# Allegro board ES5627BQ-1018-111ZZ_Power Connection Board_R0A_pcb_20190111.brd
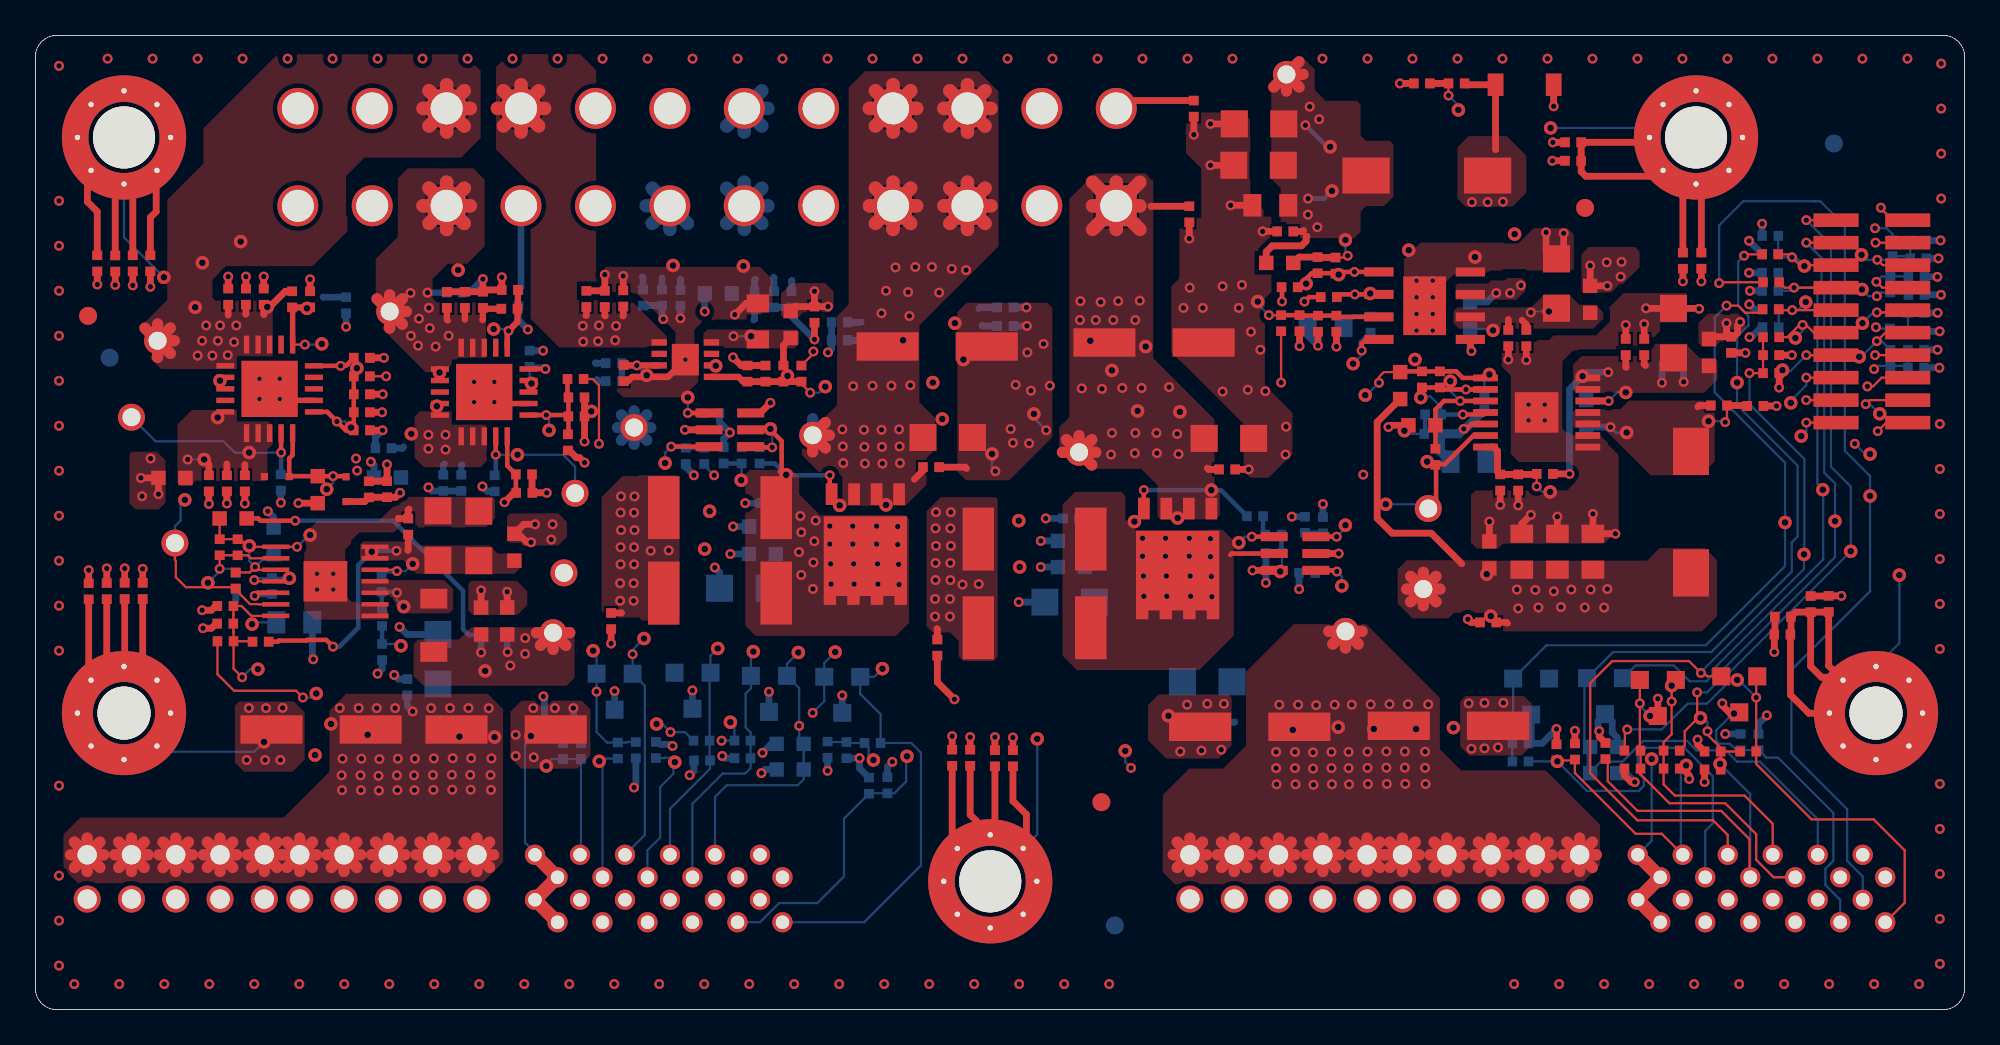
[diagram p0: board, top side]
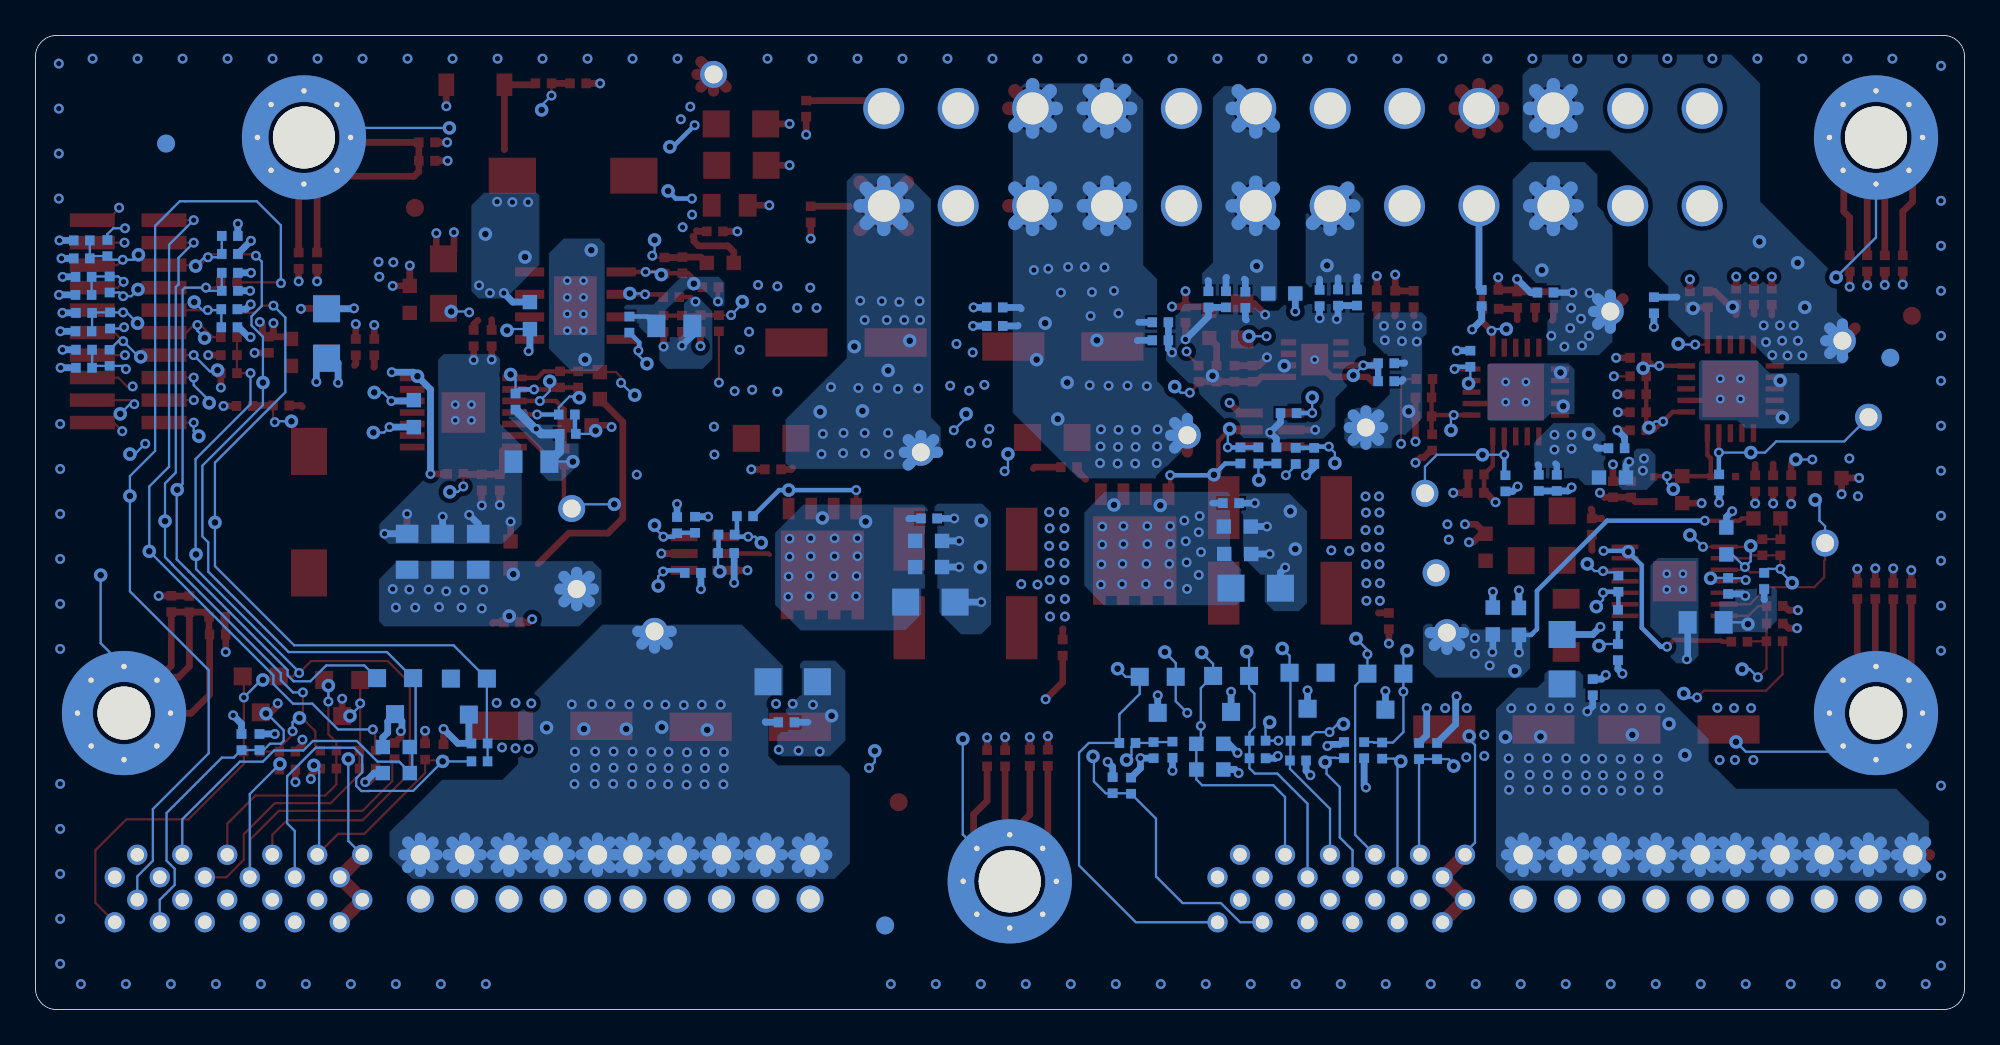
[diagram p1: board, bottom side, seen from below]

Outline 108.9 x 55 mm; copper layers: TOP, G2, S3, V4, V5, V6, G7, BOTTOM. Coordinates in mm from the lower left corner of the outline.
Outline path: 0,53.8 arc(0.35,54.65) 1.2,55 107.7,55 arc(108.55,54.65) 108.9,53.8 108.9,1.2 arc(108.55,0.35) 107.7,0 1.2,0 arc(0.35,0.35) 0,1.2 0,53.8

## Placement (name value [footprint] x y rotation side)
C1  0.1uF/16V  [CC0402]  6.06 23.64 180 top
C2  0.1uF/16V  [CC0402]  54.16 14.19 180 top
C3  0.1uF/16V  [CC0402]  4.03 23.63 180 top
C4  0.1uF/16V  [CC0402]  55.18 14.19 180 top
C5  3300pF  [CC0402]  78.85 32.5 270 bottom
C6  1uF/16V  [CC0603]  78.27 32.99 90 top
C7  22uF/16V  [CC1206]  69.07 50 270 top
C8  22uF/16V  [CC1206]  69.05 47.67 270 top
C9  22pF/50V  [CC0402]  79.28 35.58 0 top
C10  0.1uF/16V  [CC0402]  5.04 23.64 180 top
C11  0.1uF/16V  [CC0402]  3.01 23.61 180 top
C12  0.1uF/16V  [CC0402]  51.75 14.22 180 top
C13  0.1uF/16V  [CC0402]  52.77 14.22 180 top
C14  10nF/50V  [CC0402]  82.69 29.76 0 top
C15  @10uF/16V  [CC0805]  69.71 45.41 270 top
C16  0.1uF/16V  [CC0402]  70.55 43.93 270 top
C17  0.1uF/16V  [CC0402]  36.41 40.18 180 bottom
C18  0.1uF/16V  [CC0402]  82 21.86 270 top
C19  0.1uF/16V  [CC0402]  89.77 37.41 180 top
C20  1nF/50V  [CC0402]  90.82 37.41 180 top
C21  22uF/16V  [CC1206]  92.47 38.19 180 top
C22  22uF/16V  [CC1206]  92.47 38.17 0 bottom
C23  @10uF/6.3V  [CC0603]  82.08 25.67 180 top
C24  0.1uF/50V  [CC0603]  80.99 39.18 0 bottom
C25  1uF  [CC0603]  58.48 26.46 90 bottom
C26  @2200pF/50V  [CC0402]  95.03 34.1 270 top
C27  1nF/50V  [CC0402]  83.14 37.91 0 top
C28  0.1uF/16V  [CC0402]  84.16 37.91 0 top
C29  0.1uF/50V  [CC0603]  87.54 33.65 180 bottom
C30  22uF/16V  [CC1206]  85.86 40.99 180 top
C31  10uF  [CC0603]  58.48 24.99 90 bottom
C33  0.1uF/16V  [CC0402]  95.72 37.53 0 top
C34  22uF/16V  [CC1206]  51.5 32.3 270 top
C35  @0.1uF/16V  [CC0402]  41.41 28.59 90 bottom
C36  @0.1uF/16V  [CC0402]  50.56 30.62 90 top
C37  22uF/16V  [CC1206]  40.02 23.79 270 bottom
C38  @22uF/6.3V  [CC0805]  87.92 25.85 0 bottom
C39  22uF/6.3V  [CC0805]  85.91 25.85 0 bottom
C40  22uF/6.3V  [CC0805]  83.91 25.85 0 bottom
C41  0.47uF /16V  [CC0402]  73.01 40.23 270 top
C42  8200pF/16V  [CC0402]  75.37 38.68 0 bottom
C43  22pF/50V  [CC0402]  73.39 42 0 top
C45  @270uF/16V  [CAPALE_6D3PI_5D6_2SP_6D6WL7D6H]  50.9 37.44 270 top
C46  0.1uF/16V  [CC0402]  66.51 16.22 90 bottom
C47  0.1uF/16V  [CC0402]  86.8 48.96 270 top
C48  22uF/16V  [CC1206]  66.15 18.51 270 bottom
C49  0.1uF/16V  [CC0402]  4.5 42.12 0 top
C50  0.1uF/16V  [CC0402]  3.49 42.13 0 top
C51  10uF  [CC0603]  41.03 25.72 90 bottom
C54  270uF/16V  [CAPALE_6D3PI_5D6_2SP_6D6WL7D6H]  16.12 15.81 90 top
C55  270uF/16V  [CAPALE_6D3PI_5D6_2SP_6D6WL7D6H]  26.57 15.81 270 top
C56  270uF/16V  [CAPALE_6D3PI_5D6_2SP_6D6WL7D6H]  79.76 16.02 270 top
C57  270uF/16V  [CAPALE_6D3PI_5D6_2SP_6D6WL7D6H]  68.55 15.97 90 top
C58  22uF/16V  [CC1206]  22.72 19.78 180 bottom
C59  0.1uF/16V  [CC0402]  40.6 40.07 180 bottom
C60  0.1uF/16V  [CC0402]  86.8 47.92 270 top
C61  0.1uF/16V  [CC0402]  93 42.28 0 top
C62  0.1uF/16V  [CC0402]  20.99 18.2 0 bottom
C63  0.1uF/16V  [CC0402]  10.72 22.78 270 top
C64  3.3nF  [CC0402]  13.35 23.92 180 bottom
C65  @47pF  [CC0402]  11.42 26.1 0 top
C66  @0.1uF/16V  [CC0402]  67.27 30.5 90 top
C67  0.1uF/16V  [CC0402]  94.04 42.28 0 top
C68  0.1uF/16V  [CC0402]  5.5 42.13 0 top
C69  22uF/16V  [CC1206]  67.37 32.25 270 top
C70  @270uF/16V  [CAPALE_6D3PI_5D6_2SP_6D6WL7D6H]  63.15 37.66 270 top
C72  22uF/16V  [CC1206]  25.03 26.74 180 top
C73  22uF/16V  [CC1206]  22.72 26.76 180 top
C74  0.1uF/16V  [CC0402]  21.04 27.27 180 top
C75  0.1uF/16V  [CC0402]  98.61 21.18 270 top
C76  0.1uF/16V  [CC0402]  100.21 22.89 180 top
C77  0.1uF/16V  [CC0402]  98.65 22.18 270 top
C78  0.1uF/16V  [CC0402]  101.23 22.9 180 top
C79  22uF/6.3V  [CC0603]  26.63 21.94 180 top
C80  22uF/6.3V  [CC0603]  25.16 21.91 0 bottom
C83  10uF/10V  [CC0402]  12.89 40.25 180 top
C85  10uF/10V  [CC0402]  11.88 40.25 180 top
C86  0.1uF/16V  [CC0402]  10.88 40.25 180 top
C87  1000pF /50V  [CC0402]  18.43 36.8 90 top
C88  0.1uF/16V  [CC0402]  31.1 40.12 180 top
C89  0.1uF/16V  [CC0402]  18.43 32.71 90 top
C90  10uF  [CC0402]  10.81 29.71 0 top
C91  4.7uF  [CC0603]  15.94 29.35 0 top
C92  10uF  [CC0402]  11.82 29.71 0 top
C93  0.1uF/16V  [CC0402]  9.79 29.71 0 top
C94  0.1uF/16V  [CC0402]  30.54 34.56 90 top
C95  10uF  [CC0402]  27.58 30.22 90 top
C96  1000pF /50V  [CC0402]  27.9 36.75 0 bottom
C97  0.1uF/16V  [CC0402]  27.59 29.18 90 top
C98  0.1uF/16V  [CC0402]  65.14 44.9 180 top
C99  10uF  [CC0402]  24.04 29.74 180 bottom
C100  10uF/10V  [CC0402]  25.26 40.07 180 top
C101  0.1uF/16V  [CC0402]  23.02 29.74 180 bottom
C102  0.1uF/16V  [CC0402]  23.23 40.07 180 top
C103  10uF  [CC0402]  19.64 31.69 90 bottom
C104  10uF/10V  [CC0402]  24.24 40.07 180 top
C105  0.1uF/16V  [CC0402]  17.54 39.77 180 bottom
C106  0.1uF/16V  [CC0402]  23.66 40.48 90 bottom
C107  0.1uF/16V  [CC0402]  65.39 50.87 0 top
C108  0.1uF 16V  [CC0402]  43.98 39.24 180 top
C110  0.1uF/16V  [CC0402]  27.26 40.18 0 bottom
C111  10uF/16V  [CC0805]  40.78 38.85 0 top
C113  0.1uF/16V  [CC0402]  40.19 35.91 180 top
C115  0.1uF/16V  [CC0402]  45.4 37.79 90 bottom
C116  0.1uF/16V  [CC0402]  34.3 40.2 0 bottom
C117  0.1uF/16V  [CC0402]  35.37 40.2 180 bottom
C118  0.1uF/16V  [CC0402]  54.75 38.6 90 bottom
C119  0.1uF/16V  [CC0402]  33.18 40.15 180 top
C120  0.1uF/16V  [CC0402]  41.69 40.1 180 bottom
C121  0.1uF/16V  [CC0402]  42.68 40.1 0 bottom
C122  0.1uF/16V  [CC0402]  54.75 39.64 90 bottom
C123  10uF/10V  [CC0402]  32.14 40.12 180 top
C124  100pF  [CC0402]  32.65 36.49 90 bottom
C127  0.1uF/16V  [CC0402]  45.4 38.8 90 bottom
C128  @0.1uF/16V  [CC0402]  58.46 27.73 90 bottom
C129  22uF/16V  [CC1206]  58.38 23 270 bottom
C131  0.1uF/16V  [CC0402]  32.5 21.94 0 top
C132  0.22uF  [CC0402]  38.16 33.67 270 bottom
C133  0.01uF/25V  [CC0402]  38.85 31.29 180 bottom
C134  0.1uF/16V  [CC0402]  50.91 20.44 0 top
C135  0.22uF  [CC0402]  71.79 24.66 90 bottom
C136  0.01uF/25V  [CC0402]  69.91 25.77 270 bottom
C137  1uF  [CC0603]  41.06 27.27 90 bottom
CB3  @2200pF/50V  [CC0402]  78.27 52.29 270 top
CB4  0.1uF/16V  [CC0402]  72.4 38.73 180 top
CB5  @22uF/6.3V  [CC0805]  83.91 25.85 180 top
CB6  22uF/6.3V  [CC0805]  85.91 25.85 180 top
CB7  @22uF/6.3V  [CC0805]  87.92 25.85 180 top
CB8  0.1uF/16V  [CC0402]  6.49 42.13 0 top
CB9  1uF/16V  [CC0603]  13.45 26.46 180 bottom
CB10  0.1uF/25V  [CC0402]  19.54 24.05 180 bottom
CB11  22uF/6.3V  [CC0603]  26.63 21.94 0 bottom
CB12  0.1UF /50V  [CC0603]  25.16 21.94 180 top
CB13  0.1uF/16V  [CC0402]  19.85 29.38 180 top
CB14  10uF  [CC0402]  18.82 29.37 180 top
CB54  @2.2nF  [CC0402]  19.57 20.19 0 bottom
CONN1  @Vmonitor_3V3_PG  [CONN_1DP_2D54WL8D94H_PIP]  78.63 28.29 0 top
CONN2  @USB_VCC5P0  [CONN_1DP_2D54WL8D94H_PIP]  70.62 52.8 180 top
CONN4  @Vmonitor_3V3  [CONN_1DP_2D54WL8D94H_PIP]  78.35 23.74 0 top
CONN5  @VCC12  [CONN_1DP_2D54WL8D94H_PIP]  43.88 32.43 270 top
CONN6  @PSU2_VCC12  [CONN_1DP_2D54WL8D94H_PIP]  73.95 21.35 0 top
CONN7  @PSU1_VCC12  [CONN_1DP_2D54WL8D94H_PIP]  29.83 24.66 0 top
CONN8  @Heater_VCC12  [CONN_1DP_2D54WL8D94H_PIP]  58.92 31.46 0 top
CONN9  @FPGA_1V2_PG  [CONN_1DP_2D54WL8D94H_PIP]  7.87 26.34 0 top
CONN10  @FPGA_1V2  [CONN_1DP_2D54WL8D94H_PIP]  29.22 21.28 0 top
CONN11  @CPLD_VDD1P8  [CONN_1DP_2D54WL8D94H_PIP]  6.9 37.76 0 top
CONN13  @CPLD_VDD1P8_PG  [CONN_1DP_2D54WL8D94H_PIP]  5.42 33.44 0 top
CONN14  @MANG_1P2_PG  [CONN_1DP_2D54WL8D94H_PIP]  30.46 29.15 180 top
CONN15  @MANG_1P2  [CONN_1DP_2D54WL8D94H_PIP]  20 39.41 180 top
CONN16  @FPGA_2V5  [CONN_1DP_2D54WL8D94H_PIP]  33.79 32.86 0 top
CONN19  LCB25-G2024S01C-04  [CONNM_1D27X4D05_2X10SP_27D2W]  103.67 38.85 90 top
CONN20  MINI-FIT  [CONN_4D2X5D5_12X2DP_52W_PIP]  37.91 48.13 0 top
CONNB1  HI POWER  [CONN_2D54_44DP_43D7W7D5H_PIP]  40.9 8.74 180 bottom
CONNB2  HI POWER  [CONN_2D54_44DP_43D7W7D5H_PIP]  103.15 8.74 180 bottom
D1  BAT54TS  [SOD523_1D4_2SP_1D2WD8L]  17.54 29.38 90 top
DB1  @SS1040  [SOD123_3D28_2SP_AC]  84.06 52.21 90 top
DB2  BAT54TS  [SOD523_1D4_2SP_1D2WD8L]  13.62 30.09 0 top
H1  SCREW_8_2  [MTH_276C118D_8DP_OSP]  5 16.74 0 top
H2  SCREW_8_2  [MTH_276C138D_8DP_OSP]  53.9 7.24 0 top
H3  SCREW_8_2  [MTH_276C138D_8DP_OSP]  93.74 49.24 0 top
H4  SCREW_8_2  [MTH_276C138D_8DP_OSP]  5 49.24 0 top
H5  SCREW_8_2  [MTH_276C118D_8DP_OSP]  103.9 16.74 0 top
L1  3.3uH/9.5A/22mohm  [IND_6D1_2SP_7D3W7D5L6H_1]  78.55 47.08 180 top
L2  100MHz /5A  [LC0603]  94.47 37.1 0 top
L3  2.2uH  [IND_6D1_2SP_7D3W7D5L6H_1]  93.46 28.08 270 top
L4  100MHz/5A  [LC0603]  38.54 40.43 90 bottom
L5  100MHz/3A  [LC0603]  27.04 26.1 180 top
L6  2.2uH/ 3.5A 65mohm  [IND_3D_2SP_3D5W3D2L2H]  22.49 21.7 90 top
L7  100MHz/3A  [LC0603]  7.71 30.02 90 top
L8  100MHz/3A  [LC0603]  19.87 30.04 270 bottom
L9  100MHz/3A  [LC0603]  42.63 38.68 0 top
LB1  100MHz/3A  [LC0603]  87.77 40.1 0 top
NOREF  -  []  14.81 45.38 0 top
NOREF#2  -  []  0 0 0 top
NOREF#3  -  []  103.67 38.85 0 top
NOREF#4  -  [unnamed#2]  2.97 39.17 0 top
NOREF#5  -  []  93.74 49.24 0 top
NOREF#6  -  []  2.92 8.74 0 top
NOREF#7  -  []  5 16.74 0 top
NOREF#8  -  []  103.9 16.74 0 top
NOREF#9  -  []  65.17 8.74 0 top
NOREF#10  -  []  107.7 55 0 top
NOREF#11  -  []  2.92 8.74 0 top
NOREF#12  -  []  5 49.24 0 top
NOREF#13  -  []  53.9 7.24 0 top
NOREF#14  -  []  -286.37 -149.01 0 top
NOREF#15  -  []  93.74 49.24 0 top
NOREF#16  -  [unnamed#2]  87.48 45.26 0 top
NOREF#17  -  []  5 49.24 0 top
NOREF#18  -  []  103.9 16.74 0 top
NOREF#19  -  []  53.9 7.24 0 top
NOREF#20  -  []  -319.22 -224.39 0 top
NOREF#21  -  []  61.72 -23.77 0 top
NOREF#22  -  []  14.81 45.38 0 top
NOREF#23  -  []  0 0 0 top
NOREF#24  -  [unnamed#2]  60.17 11.71 0 top
NOREF#25  -  []  5 16.74 0 top
NOREF#26  -  []  108.9 1.2 0 top
NOREF#27  -  []  65.17 8.74 0 top
NOREF#28  -  []  103.67 38.85 0 top
NOREF#29  -  []  94.52 27.73 180 bottom
NOREF#30  -  [unnamed#2]  101.52 48.9 180 bottom
NOREF#31  -  [unnamed#2]  60.93 4.75 180 bottom
NOREF#32  -  []  66.89 47.69 180 bottom
NOREF#33  -  [unnamed#2]  4.19 36.8 180 bottom
Q3  PJMBZ6V2  [SOT23_3SP_C1_C2_A]  41.41 17.82 0 bottom
Q4  PJMBZ6V2  [SOT23_3SP_C1_C2_A]  45.55 17.77 0 bottom
Q5  PJMBZ6V2  [SOT23_3SP_C1_C2_A]  91.58 17.59 180 top
Q6  PJMBZ6V2  [SOT23_3SP_C1_C2_A]  88.6 17.7 0 bottom
Q7  PJMBZ6V2  [SOT23_3SP_C1_C2_A]  32.69 17.95 0 bottom
Q8  PJMBZ6V2  [SOT23_3SP_C1_C2_A]  37.09 18 0 bottom
Q11  N-CH  [SO8_3D75X1D27_5SP]  46.85 26.28 90 top
Q12  N-CH  [SO8_3D75X1D27_5SP]  64.48 25.46 90 top
QB1  PJMBZ6V2  [SOT23_3SP_C1_C2_A]  96.18 17.8 180 top
QB2  PJMBZ6V2  [SOT23_3SP_C1_C2_A]  84.43 17.67 0 bottom
R1  22.1K  [RC0402]  81.8 34.33 180 bottom
R2  73.2K  [RC0402]  78.27 35.58 180 top
R3  0  [RC0402]  78.9 33.6 90 bottom
R4  100K  [RC0402]  79.03 31.21 180 top
R5  10ohm  [RC0603]  77.04 35.23 0 top
R6  0ohm 0805  [RC0805]  80.9 30.94 90 bottom
R7  @10K  [RC0402]  83.7 29.76 180 top
R8  10K  [RC0402]  85.2 30.24 270 top
R9  @2.2  [RC0402]  97.09 34.08 90 top
R12  0ohm 0805  [RC0805]  72.83 38.6 270 bottom
R13  22.1Kohm  [RC0402]  70.8 40.78 90 top
R14  0  [RC0402]  71.36 38.75 0 top
R15  @0  [RC0402]  70.32 38.75 0 top
R16  124Kohm  [RC0402]  72.38 42.03 180 top
R17  10ohm  [RC0603]  70.24 42.16 270 top
R18  @4.7K  [RC0402]  97.93 43.68 270 bottom
R19  @4.7K  [RC0402]  97.93 42.66 90 bottom
R20  @10K  [RC0402]  106.18 38.3 90 bottom
R21  @4.7K  [RC0402]  106.16 39.34 270 bottom
R22  10  [RC0402]  104.71 36.8 180 bottom
R24  9.1K  [RC0603]  88.53 14.83 90 bottom
R25  @10K  [RC0603]  88.53 13.35 270 bottom
R26  @10K  [RC0603]  42.61 13.56 90 bottom
R27  9.1K  [RC0603]  42.61 15 270 bottom
R28  10  [RC0402]  104.84 42.99 0 bottom
R29  @4.7K  [RC0402]  106.28 42.41 270 bottom
R30  @4.7K  [RC0402]  106.28 43.43 90 bottom
R31  510  [RC0402]  106.18 41.37 270 bottom
R32  @4.7K  [RC0402]  45.78 14.65 180 bottom
R33  4.7K  [RC0402]  44.71 14.67 0 bottom
R34  10  [RC0402]  47.25 15.05 270 bottom
R35  0  [RC0402]  92.36 14.62 90 top
R36  0  [RC0402]  90.16 14.62 270 top
R37  10  [RC0402]  97.93 42.64 270 top
R38  @1000  [RC0402]  97.93 41.6 270 bottom
R39  510  [RC0402]  97.93 40.58 90 bottom
R40  10  [RC0402]  104.68 38.91 180 bottom
R41  3.83Kohm  [RC0402]  33.89 14.65 180 bottom
R42  100ohm  [RC0402]  106.16 36.24 90 bottom
R43  @4.7K  [RC0402]  106.16 37.25 270 bottom
R44  0  [RC0402]  35.03 14.66 0 bottom
R45  0  [RC0402]  37.6 15.18 90 bottom
R46  0  [RC0402]  39.91 15.18 90 bottom
R47  4.7K(1%)  [RC0402]  47.05 12.64 180 bottom
R48  @1000  [RC0402]  106.18 40.35 90 bottom
R49  4.7K(1%)  [RC0402]  29.78 14.6 0 bottom
R51  10  [RC0402]  97.98 41.06 270 top
R52  @680(1%)  [RC0402]  48.09 12.67 180 bottom
R53  10  [RC0402]  104.71 40.94 180 bottom
R54  @680(1%)  [RC0402]  30.8 14.6 0 bottom
R55  0  [RC0402]  32.88 14.62 0 bottom
R56  @1K  [RC0402]  12.71 20.77 90 top
R57  0  [RC0402]  10.73 20.79 270 top
R58  1K  [RC0402]  10.72 21.79 90 top
R59  100K  [RC0402]  11.3 24.23 180 top
R60  22.1K  [RC0402]  11.31 24.2 0 bottom
R61  12.7Kohm  [RC0402]  10.4 26.1 180 top
R62  10ohm  [RC0603]  11.16 27.73 90 top
R63  2.87K  [RC0402]  15.5 40.1 0 top
R64  3.57K  [RC0402]  14.49 40.1 0 top
R65  0  [RC0402]  18.43 35.76 90 top
R66  @4.7K  [RC0402]  18.43 34.74 270 top
R67  10K  [RC0402]  13.85 29.76 0 bottom
R68  1K(5%)  [RC0402]  30.54 33.49 270 top
R69  4.99K  [RC0402]  26.78 40.63 90 top
R70  2.49K  [RC0402]  26.76 39.57 90 top
R71  10K  [RC0402]  25.92 29.71 0 bottom
R72  @1K  [RC0402]  42.23 35.91 180 top
R73  1K  [RC0402]  41.21 35.91 0 top
R74  0  [RC0402]  43.24 35.91 180 top
R75  39.2K  [RC0402]  32.65 35.48 90 bottom
R76  36.5K  [RC0402]  33.21 35.93 180 top
R78  10K  [RC0402]  36.71 31.26 180 bottom
R79  10K  [RC0402]  37.75 31.26 180 bottom
R80  100  [RC0402]  39.86 31.29 180 bottom
R81  100  [RC0402]  40.88 31.29 180 bottom
R83  10K  [RC0402]  72.68 27.35 0 bottom
R84  1.5K  [RC0402]  71.66 27.37 0 bottom
R85  100  [RC0402]  69.89 26.81 270 bottom
R86  100  [RC0402]  68.84 27.86 90 bottom
R87  0.002ohm\1W/2512  [RC2512]  38.64 28.34 90 top
R88  0.002ohm\1W/2512  [RC2512]  38.64 23.51 90 top
R90  0.002ohm\1W/2512  [RC2512]  56.4 21.56 90 top
R91  @4.7K  [RC0402]  37.63 14.06 90 bottom
R92  @4.7K  [RC0402]  39.91 14.19 90 bottom
R93  @4.7K  [RC0402]  92.36 13.61 90 top
R94  @4.7K  [RC0402]  90.16 13.61 270 top
R95  0.002ohm\1W/2512  [RC2512]  56.4 26.56 90 top
RB2  @2.2  [RC0402]  80.22 52.29 90 top
RB3  1K(5%)  [RC0402]  73.44 38.73 180 top
RB5  @10K  [RC0402]  97.95 39.54 270 bottom
RB6  @4.7K  [RC0402]  97.95 38.52 90 bottom
RB7  10  [RC0402]  97.95 39.54 270 top
RB8  100ohm  [RC0402]  97.98 36.95 270 top
RB9  @4.7K  [RC0402]  97.98 35.93 90 top
RB10  10  [RC0402]  97.98 37.97 270 top
RB11  10  [RC0402]  96.68 14.57 90 top
RB12  @4.7K  [RC0402]  94.68 14.57 270 top
RB13  4.7K  [RC0402]  94.68 13.56 90 top
RB14  3.83Kohm  [RC0402]  83.83 15.03 270 bottom
RB15  @4.7K  [RC0402]  86.9 14.57 180 top
RB16  @4.7K  [RC0402]  96.25 15.11 180 bottom
RB17  680(1%)  [RC0402]  97.27 15.11 180 bottom
RB18  0  [RC0402]  83.83 14.01 90 bottom
RB19  680(1%)  [RC0402]  85.86 14.52 180 top
RB20  0  [RC0402]  88.63 14.6 180 top
RB21  0ohm 0805  [RC0805]  14.62 21.86 270 bottom
RB22  1K(5%)  [RC0402]  18.43 33.72 270 top
RB23  @4.7K  [RC0402]  30.06 32.02 180 top
RB24  0  [RC0402]  30.49 35.6 90 top
RB25  @1.5ohm  [RC0402]  19.57 22.12 180 bottom
U1  TPS54626PWPR  [TSSOP_D65X5D775_14SP_4D4W5L_G1]  84.74 33.71 0 top
U2  TPS54329DDAR  [SOP_1D27X5D165_8SP_3D9W_G95X130]  78.42 39.74 180 top
U3  TPS54226PWPR  [TSSOP_D65X5D6_14SP_GP]  16.37 24.18 0 top
U4  TPS74801RGWR  [QFN_D65X5D_20SP_5WL_G1]  13.22 35.04 90 top
U5  TPS74801RGWR  [QFN_D65X5D_20SP_5WL_G1]  25.33 34.87 90 top
U6  TPS73701DRBR  [QFN_D65X2D95_8SP_3WL1H_G1]  36.69 36.7 0 top
U7  ADM4210-1AUJ-RL7  [SOT23_D95X2D35_6SP_1D6W2D9L]  39.2 32.73 270 top
U8  ADM4210-1AUJ-RL7  [SOT23_D95X2D35_6SP_1D6W2D9L]  71.11 25.75 90 top

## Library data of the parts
C1-C31 C33-C43 C46-C51 C58-C69 C75-C80 C83 C85-C108 C110 C113 C115-C124 C127-C129 C132 C135 C137 CB3-CB8 CB10 CB11 CB13 CB14 CB54 = C_NP
C45 C54-C57 C70 = C_P
C72 C73 C131 C134 CB9 = CAP NP
C74 = C_NP: room: U119
C111 CB12 = C_NP: room: 1
C133 C136 = C_NP: room: VCC10
CONN1 CONN2 CONN4-CONN11 CONN13-CONN16 = PINSTICK_MALE_1PX1R
CONN19 = PIN HEADER_MALE_10PX2R
CONN20 = CONN_POWER_MALE_12PX2R
CONNB1 CONNB2 = CONN_POWER_FEMALE_DIP44_2
D1 DB1 DB2 = DIODE1_1
H1-H5 = SCREW_8_1
L1 L3 L6 = POWER CHOKE
L2 L4 L5 L7-L9 LB1 = BEAD
Q3-Q8 QB1 QB2 = DIODE2_3
Q11 Q12 = NMOS1_6
R1-R7 R9 R12 R13 R16 R17 R24-R27 R35 R36 R41 R44-R47 R49 R52 R54-R56 R58-R64 R66 R68-R70 R72 R73 R75 R76 R80 R81 R85-R88 R90-R95 RB2 RB3 RB14-RB23 RB25 = R: tolerance: 1%
R8 R67 R71 = R: tolerance: 1%; room: 71
R14 R15 R57 R65 R74 RB24 = R: tolerance: 1%; room: U120
R18-R22 R28-R34 R37-R40 R42 R43 R48 R51 R53 RB5-RB13 = R: tolerance: 1%; room: U111
R78 R79 R83 R84 = R
U1 = DC_DC_TI_TPS54626
U2 = DC_DC_MPS_MP1484EN-C166_0
U3 = DC_DC_TI_TPS54226_PWP
U4 U5 = LDO_TI_TPS74801RGW_1
U6 = LDO_TI_TPS73701
U7 U8 = HOT SWAP_ADI_ADM4210-1AUJ

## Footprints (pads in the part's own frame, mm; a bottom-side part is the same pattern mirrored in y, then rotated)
CAPALE_6D3PI_5D6_2SP_6D6WL7D6H
  rect 1.6x3.505 smd: A(0,-2.8) C(0,2.8)
CC0402
  rect 0.559x0.539 smd: 1(0,0.454) 2(0,-0.454)
CC0603
  rect 0.813x0.813 smd: 1(0,0.762) 2(0,-0.762)
CC0805
  rect 1.27x1.016 smd: 1(0,1.016) 2(0,-1.016)
CC1206
  rect 1.524x1.524 smd: 1(0,1.397) 2(0,-1.397)
CONN_1DP_2D54WL8D94H_PIP
  round 1.524 hole 1.016: 1(0,0)
CONN_2D54_44DP_43D7W7D5H_PIP
  round 1.143 hole 0.762: 1(-1.27,-3.81) 2(0,-2.54) 3(1.27,-3.81) 4(2.54,-2.54) 5(3.81,-3.81) 6(5.08,-2.54) 7(6.35,-3.81) 8(7.62,-2.54) 9(8.89,-3.81) 10(10.16,-2.54) 11(11.43,-3.81) 12(12.7,-2.54) 13(12.7,0) 14(11.43,-1.27) 15(10.16,0) 16(8.89,-1.27) 17(7.62,0) 18(6.35,-1.27) 19(5.08,0) 20(3.81,-1.27) 21(2.54,0) 22(1.27,-1.27) 23(0,0) 24(-1.27,-1.27)
  round 1.524 hole 1.092: P1A_1(15.98,-2.5) P1A_2(18.48,-2.5) P1A_3(20.98,-2.5) P1A_4(23.48,-2.5) P1A_5(25.98,-2.5) P1B_1(15.98,0) P1B_2(18.48,0) P1B_3(20.98,0) P1B_4(23.48,0) P1B_5(25.98,0) P2A_1(27.98,-2.5) P2A_2(30.48,-2.5) P2A_3(32.98,-2.5) P2A_4(35.48,-2.5) P2A_5(37.98,-2.5) P2B_1(27.98,0) P2B_2(30.48,0) P2B_3(32.98,0) P2B_4(35.48,0) P2B_5(37.98,0)
CONN_4D2X5D5_12X2DP_52W_PIP
  rect 2.311x2.311 hole 1.803: 1(23.1,-2.75)
  round 2.311 hole 1.803: 2(18.9,-2.75) 3(14.7,-2.75) 4(10.5,-2.75) 5(6.3,-2.75) 6(2.1,-2.75) 7(-2.1,-2.75) 8(-6.3,-2.75) 9(-10.5,-2.75) 10(-14.7,-2.75) 11(-18.9,-2.75) 12(-23.1,-2.75) 13(23.1,2.75) 14(18.9,2.75) 15(14.7,2.75) 16(10.5,2.75) 17(6.3,2.75) 18(2.1,2.75) 19(-2.1,2.75) 20(-6.3,2.75) 21(-10.5,2.75) 22(-14.7,2.75) 23(-18.9,2.75) 24(-23.1,2.75)
CONNM_1D27X4D05_2X10SP_27D2W
  rect 0.762x2.54 smd: 1(-5.715,-2.025) 2(-5.715,2.025) 3(-4.445,-2.025) 4(-4.445,2.025) 5(-3.175,-2.025) 6(-3.175,2.025) 7(-1.905,-2.025) 8(-1.905,2.025) 9(-0.635,-2.025) 10(-0.635,2.025) 11(0.635,-2.025) 12(0.635,2.025) 13(1.905,-2.025) 14(1.905,2.025) 15(3.175,-2.025) 16(3.175,2.025) 17(4.445,-2.025) 18(4.445,2.025) 19(5.715,-2.025) 20(5.715,2.025)
IND_3D_2SP_3D5W3D2L2H
  rect 1.118x1.524 smd: 1(1.5,0) 2(-1.5,0)
IND_6D1_2SP_7D3W7D5L6H_1
  rect 2.667x2.032 smd: 1(-3.431,0) 2(3.431,0)
LC0603
  rect 0.813x0.813 smd: 1(0,0.762) 2(0,-0.762)
MTH_276C118D_8DP_OSP
  round 2.997 hole 2.997 unplated: (0,0)
  round 0.889 hole 0.305: 1(0,2.629) 2(1.859,1.859) 3(2.629,0) 4(1.859,-1.859) 5(0,-2.629) 6(-1.859,-1.859) 7(-2.629,0) 8(-1.859,1.859)
MTH_276C138D_8DP_OSP
  round 3.505 hole 3.505 unplated: (0,0)
  round 0.889 hole 0.305: 1(0,2.629) 2(1.859,1.859) 3(2.629,0) 4(1.859,-1.859) 5(0,-2.629) 6(-1.859,-1.859) 7(-2.629,0) 8(-1.859,1.859)
QFN_D65X2D95_8SP_3WL1H_G1
  rect 0.864x0.356 smd: 1(-1.475,0.975) 2(-1.475,0.325) 3(-1.475,-0.325) 4(-1.475,-0.975) 5(1.475,-0.975) 6(1.475,-0.325) 7(1.475,0.325) 8(1.475,0.975)
  rect 1.524x1.778 smd: G1(0,0)
QFN_D65X5D_20SP_5WL_G1
  rect 0.305x1.016 smd: 1(1.3,2.5) 2(0.65,2.5) 3(0,2.5) 4(-0.65,2.5) 5(-1.3,2.5) 11(-1.3,-2.5) 12(-0.65,-2.5) 13(0,-2.5) 14(0.65,-2.5) 15(1.3,-2.5)
  rect 1.016x0.305 smd: 6(-2.5,1.3) 7(-2.5,0.65) 8(-2.5,0) 9(-2.5,-0.65) 10(-2.5,-1.3) 16(2.5,-1.3) 17(2.5,-0.65) 18(2.5,0) 19(2.5,0.65) 20(2.5,1.3)
  rect 3.175x3.175 smd: G1(0,0)
RC0402
  rect 0.559x0.539 smd: 1(0,0.454) 2(0,-0.454)
RC0603
  rect 0.813x0.813 smd: 1(0,0.762) 2(0,-0.762)
RC0805
  rect 1.27x1.016 smd: 1(0,1.016) 2(0,-1.016)
RC2512
  rect 3.556x1.778 smd: 1(0,3.175) 2(0,-3.175)
SO8_3D75X1D27_5SP
  rect 1.219x0.66 smd: 1(2.825,-1.905) 2(2.825,-0.635) 3(2.825,0.635) 4(2.825,1.905)
  custom 1.175x1.175 smd: 5(-0.925,0)
SOD123_3D28_2SP_AC
  rect 1.27x0.889 smd: A(0,-1.64) C(0,1.64)
SOD523_1D4_2SP_1D2WD8L
  rect 0.406x0.406 smd: A(-0.7,0) C(0.7,0)
SOP_1D27X5D165_8SP_3D9W_G95X130
  rect 1.651x0.508 smd: 1(-2.582,1.905) 2(-2.582,0.635) 3(-2.582,-0.635) 4(-2.582,-1.905) 5(2.582,-1.905) 6(2.582,-0.635) 7(2.582,0.635) 8(2.582,1.905)
  rect 2.413x3.302 smd: G1(0,0)
SOT23_3SP_C1_C2_A
  rect 1.016x1.016 smd: A(0,1.016) C1(-1.016,-1.016) C2(1.016,-1.016)
SOT23_D95X2D35_6SP_1D6W2D9L
  rect 0.508x1.524 smd: 1(-0.95,-1.175) 2(0,-1.175) 3(0.95,-1.175) 4(0.95,1.175) 5(0,1.175) 6(-0.95,1.175)
TSSOP_D65X5D6_14SP_GP
  rect 1.524x0.254 smd: 1(-2.8,1.95) 2(-2.8,1.3) 3(-2.8,0.65) 4(-2.8,0) 5(-2.8,-0.65) 6(-2.8,-1.3) 7(-2.8,-1.95) 8(2.8,-1.95) 9(2.8,-1.3) 10(2.8,-0.65) 11(2.8,0) 12(2.8,0.65) 13(2.8,1.3) 14(2.8,1.95)
  rect 2.464x2.286 smd: G1(0,0)
TSSOP_D65X5D775_14SP_4D4W5L_G1
  rect 1.397x0.381 smd: 1(-2.887,1.95) 2(-2.887,1.3) 3(-2.887,0.65) 4(-2.887,0) 5(-2.887,-0.65) 6(-2.887,-1.3) 7(-2.887,-1.95) 8(2.887,-1.95) 9(2.887,-1.3) 10(2.887,-0.65) 11(2.887,0) 12(2.887,0.65) 13(2.887,1.3) 14(2.887,1.95)
  rect 2.464x2.286 smd: G1(0,0)
unnamed#2
  round 1.016 smd: (0,0)

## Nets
5VSTB1: CONNB1.11(+5VSB#3) CONNB1.12(+5VSB#2) CONNB1.13(+5VSB#0) CONNB1.14(+5VSB#1)
5VSTB2: CONNB2.11(+5VSB#3) CONNB2.12(+5VSB#2) CONNB2.13(+5VSB#0) CONNB2.14(+5VSB#1)
AGND_FPGA_1V2: C64.2 R60.1 RB21.1 U3.5(GND)
GND: C1.2 C2.2 C3.2 C4.2 C6.1 C7.2 C8.2 C10.2 C11.2 C12.2 C13.2 C14.2 C15.2 C16.2 C17.2 C18.2 C19.2 C20.2 C21.2 C22.2 C23.2 C25.2 C27.2 C28.2 C30.2 C31.2 C33.2 C34.1 C35.2 C36.2 C37.1 C38.2 C39.2 C40.2 C41.2 C45.C C46.2 C47.2 C48.1 C49.2 C50.2 C51.2 C54.C C55.C C56.C C57.C C58.1 C59.2 C60.2 C61.2 C62.2 C63.2 C66.2 C67.2 C68.2 C69.1 C70.C C72.2 C73.2 C74.2 C75.2 C76.2 C77.2 C78.2 C79.2 C80.2 C83.2 C85.2 C86.2 C87.2 C88.2 C89.2 C90.2 C91.2 C92.2 C93.2 C94.2 C95.2 C96.2 C97.2 C98.1 C99.2 C100.2 C101.2 C102.2 C103.2 C104.2 C105.2 C106.1 C107.2 C108.1 C110.1 C111.1 C113.2 C115.2 C116.1 C117.2 C118.1 C119.2 C120.2 C121.1 C122.1 C123.2 C127.2 C128.2 C129.1 C131.2 C132.2 C133.1 C134.2 C135.2 C136.1 C137.2 CB3.2 CB4.1 CB5.2 CB6.2 CB7.2 CB8.2 CB9.1 CB11.2 CB12.2 CB13.2 CB14.2 CB54.1 CONN20.2 CONN20.5 CONN20.8 CONN20.11 CONN20.12 CONN20.14 CONN20.17 CONN20.20 CONN20.23 CONN20.24 CONNB1.P1A_1(GND#9) CONNB1.P1A_2(GND#8) CONNB1.P1A_3(GND#7) CONNB1.P1A_4(GND#6) CONNB1.P1A_5(GND#5) CONNB1.P2A_1(GND#4) CONNB1.P2A_2(GND#3) CONNB1.P2A_3(GND#2) CONNB1.P2A_4(GND#1) CONNB1.P2A_5(GND#0) CONNB2.P1A_1(GND#9) CONNB2.P1A_2(GND#8) CONNB2.P1A_3(GND#7) CONNB2.P1A_4(GND#6) CONNB2.P1A_5(GND#5) CONNB2.P2A_1(GND#4) CONNB2.P2A_2(GND#3) CONNB2.P2A_3(GND#2) CONNB2.P2A_4(GND#1) CONNB2.P2A_5(GND#0) DB1.A Q3.A Q4.A Q5.A Q6.A Q7.A Q8.A QB1.A QB2.A R6.1 R7.1 R9.2 R12.1 R18.1 R20.1 R24.1 R27.1 R30.1 R33.1 R38.1 R41.2 R42.1 R44.2 R48.1 R52.1 R54.2 R58.1 R63.1 R68.1 R69.1 R73.1 R76.1 R78.2 R83.2 RB3.1 RB5.1 RB8.1 RB13.1 RB14.2 RB17.1 RB19.2 RB20.2 RB21.2 RB22.1 U1.8(PGND1) U1.9(PGND2) U1.G1(PWGD) U2.4(GND) U2.G1 U3.8(PGND#1) U3.9(PGND#2) U3.G1(PWRPD) U4.12(GND) U4.G1 U5.12(GND) U5.G1 U6.4(GND1) U6.G1(GND PAD) U7.2(GND) U8.2(GND)
VCC12: C34.2 C36.1 C45.A C115.1 C118.2 C122.2 C127.1 CONN5.1 CONN20.3 CONN20.4 CONN20.15 CONN20.16 Q11.1(S1) Q11.2(S2) Q11.3(S3)
BS_USB_VCC5P0: C24.1 U2.1(BS)
BS_VSTB_3V3: C29.1 U1.12(VBST)
CPLD_VDD1P8: C83.1 C85.1 C86.1 C105.1 CONN11.1 CONN20.22 R64.1 U4.1(VOUT1) U4.18(VOUT2) U4.19(VOUT3) U4.20(VOUT4)
CPLD_VDD1P8_FB: R63.2 R64.2 U4.16(FB)
CPLD_VDD1P8_PG: CONN13.1 CONN19.4 R67.2 U4.9(PG)
CPLD_VDD1P8_SS: C87.1 U4.15(SS)
CPLD_VDD1P8_VIN: C90.1 C92.1 C93.1 DB2.A L7.2 U4.5(VIN1) U4.6(VIN2) U4.7(VIN3) U4.8(VIN4)
EN_CPLD_VDD1P8_R: C89.1 R65.1 R66.2 RB22.2 U4.11(EN)
EN_MANG_1P2_R: C94.1 R68.2 RB23.2 RB24.1 U5.11(EN)
EN_USB_VCC5P0_R: CB4.2 R14.1 R15.1 RB3.2 U2.7(EN)
FB_USB_VCC5P0: C43.2 R13.2 R16.1 U2.5(FB)
FB_VSTB_3V3: C9.2 R1.1 R2.1 U1.2(VFB)
FPGA_1V2: C79.1 C80.1 C110.2 CB11.1 CB12.1 CONN10.1 CONN20.9 L6.2 R62.2
FPGA_1V2_BST: CB10.1 U3.12(VBST)
FPGA_1V2_EN_R: C63.1 R56.1 R57.1 R58.2 U3.7(EN)
FPGA_1V2_FB: C65.2 R60.2 R61.1 U3.2(VFB)
FPGA_1V2_PG: CONN9.1 R59.1 U3.6(PG)
FPGA_1V2_SS: C64.1 U3.4(SS)
FPGA_1V2_SW: CB10.2 L6.1 RB25.1 U3.10(SW1) U3.11(SW2)
FPGA_1V2_VIN: C72.1 C73.1 C74.1 L5.1 R56.2 U3.13(VIN) U3.14(VCC)
FPGA_1V2_VO: C65.1 R61.2 R62.1 U3.1(VO)
FPGA_1V2_VREG5: CB9.2 R59.2 U3.3(VREG5)
FPGA_2V5: C88.1 C119.1 C123.1 C124.2 CONN16.1 CONN20.21 R75.2 U6.1(OUT)
FPGA_2V5_EN: C113.1 R72.1 R73.2 R74.1 U6.5(EN)
FPGA_2V5_FB: C124.1 R75.1 R76.2 U6.3(NR/FB)
FPGA_2V5_IN: C111.2 L9.2 R72.2 U6.8(IN)
HEATER_VCC12: C33.1 C66.1 C69.2 C70.A C98.2 CONN8.1 CONN20.1 L2.1 L5.2 LB1.1 Q12.1(S1) Q12.2(S2) Q12.3(S3)
HGATE_MB1: Q11.4(G) R81.2
HGATE_MB2: Q12.4(G) R86.2
I2C_SCL_PS1: CONNB1.19(SCL) Q8.C2 R45.1 R91.1
I2C_SCL_PS2: CONNB2.19(SCL) Q5.C1 R35.1 R93.1
I2C_SDA_PS1: CONNB1.20(SDA) Q3.C1 R46.1 R92.1
I2C_SDA_PS2: CONNB2.20(SDA) Q5.C2 R36.1 R94.1
LGND_USB_VCC5P0: C42.2 R12.2 R13.1
LGND_VSTB_3V3: C5.2 R1.2 R6.2 U1.5(GND)
MANG_1P2: C100.1 C102.1 C104.1 C106.2 CONN15.1 CONN20.10 R70.1 U5.1(VOUT1) U5.18(VOUT2) U5.19(VOUT3) U5.20(VOUT4)
MANG_1P2_FB: R69.2 R70.2 U5.16(FB)
MANG_1P2_PG: CONN14.1 CONN19.5 R71.2 U5.9(PG)
MANG_1P2_SS: C96.1 U5.15(SS)
MANG_1P2_VIN: C99.1 C101.1 C103.1 L8.2 U5.5(VIN1) U5.6(VIN2) U5.7(VIN3) U5.8(VIN4)
MB1_PWR_EN: CONN19.7 R79.2
PS1_12V_PG: CONN19.11 R20.2 R21.1 R40.1
PS1_12V_PG_R: Q7.C1 R40.2 R41.1 R55.2
PS1_A0: CONNB1.3(A0) R47.2 R52.2
PS1_A1: CONNB1.15(A1) R49.1 R54.1
PS1_AC_ALERT: CONN19.15 R28.1 R29.1 R30.2
PS1_AC_ALERT_R: CONNB1.21(PS_ALERT) Q3.C2 R26.1 R27.2 R28.2
PS1_KILL: CONNB1.18(PS_KILL) R44.1
PS1_ON: CONN19.9 R22.1
PS1_ON_R: CONNB1.17(PS_ON) Q7.C2 R22.2 R42.2 R43.1
PS1_PDB_FAULT: R32.1 R33.2 R34.1
PS1_PDB_FAULT_R: CONNB1.1(PDB_FAULT) Q4.C2 R34.2
PS1_PRESENT: CONN19.13 Q4.C1 R31.1 R48.2 R53.1
PS1_PRESENT_R: CONNB1.2(PRESENT) R53.2
PS1_PW_OK: CONNB1.16(PW_OK) R55.1
PS2_12V_PG: CONN19.12 RB5.2 RB6.1 RB7.1
PS2_12V_PG_R: QB2.C1 RB7.2 RB14.1 RB18.2
PS2_A0: CONNB2.3(A0) RB16.2 RB17.2
PS2_A1: CONNB2.15(A1) RB15.1 RB19.1
PS2_AC_ALERT: CONN19.16 R18.2 R19.1 R37.1
PS2_AC_ALERT_R: CONNB2.21(PS_ALERT) Q6.C1 R24.2 R25.1 R37.2
PS2_KILL: CONNB2.18(PS_KILL) RB20.1
PS2_ON: CONN19.10 RB10.1
PS2_ON_R: CONNB2.17(PS_ON) QB1.C2 RB8.2 RB9.1 RB10.2
PS2_PDB_FAULT: RB11.1 RB12.1 RB13.2
PS2_PDB_FAULT_R: CONNB2.1(PDB_FAULT) QB1.C1 RB11.2
PS2_PRESENT: CONN19.14 Q6.C2 R38.2 R39.1 R51.1
PS2_PRESENT_R: CONNB2.2(PRESENT) R51.2
PS2_PW_OK: CONNB2.16(PW_OK) RB18.1
PSU1_SCL: CONN19.17 R45.2
PSU1_SDA: CONN19.19 R46.2
PSU2_SCL: CONN19.18 R35.2
PSU2_SDA: CONN19.20 R36.2
PSU_VCC12: C46.1 C48.2 C54.A C55.A C56.A C57.A C58.2 C62.1 C131.1 C134.1 CONN6.1 CONN7.1 CONNB1.P1B_1(+12V#9) CONNB1.P1B_2(+12V#8) CONNB1.P1B_3(+12V#7) CONNB1.P1B_4(+12V#6) CONNB1.P1B_5(+12V#5) CONNB1.P2B_1(+12V#4) CONNB1.P2B_2(+12V#3) CONNB1.P2B_3(+12V#2) CONNB1.P2B_4(+12V#1) CONNB1.P2B_5(+12V#0) CONNB2.P1B_1(+12V#9) CONNB2.P1B_2(+12V#8) CONNB2.P1B_3(+12V#7) CONNB2.P1B_4(+12V#6) CONNB2.P1B_5(+12V#5) CONNB2.P2B_1(+12V#4) CONNB2.P2B_2(+12V#3) CONNB2.P2B_3(+12V#2) CONNB2.P2B_4(+12V#1) CONNB2.P2B_5(+12V#0) R84.2 R87.1 R88.1 R90.1 R95.1 U7.6(VCC) U8.6(VCC)
PSU_VCC12BUS: CONNB1.22(+12VBUS) CONNB2.22(+12VBUS)
SCREW1: C49.1 C50.1 C68.1 CB8.1 H4.1 H4.2 H4.3 H4.4 H4.5 H4.6 H4.7 H4.8
SCREW2: C75.1 C76.1 C77.1 C78.1 H5.1 H5.2 H5.3 H5.4 H5.5 H5.6 H5.7 H5.8
SCREW3: C1.1 C3.1 C10.1 C11.1 H1.1 H1.2 H1.3 H1.4 H1.5 H1.6 H1.7 H1.8
SCREW4: C2.1 C4.1 C12.1 C13.1 H2.1 H2.2 H2.3 H2.4 H2.5 H2.6 H2.7 H2.8
SCREW5: C47.1 C60.1 C61.1 C67.1 H3.1 H3.2 H3.3 H3.4 H3.5 H3.6 H3.7 H3.8
SENSE_12V_HEATER: C25.1 C31.1 C128.1 C129.2 Q12.5(D) R90.2 R95.2 U8.5(SENSE)
SENSE_12V_PSU: C35.1 C37.2 C51.1 C137.1 Q11.5(D) R87.2 R88.2 U7.5(SENSE)
SS_USB_VCC5P0: C42.1 U2.8(SS)
SS_VSTB_3V3: R3.1 U1.4(SS)
SS_VSTB_3V3_R: C5.1 R3.2
SW_USB_VCC5P0: C24.2 DB1.C L1.1 RB2.2 U2.3(SW)
SW_USB_VCC5P0_PLL_C: CB3.1 RB2.1
SW_VSTB_3V3: C26.2 C29.2 L3.1 U1.10(SW1) U1.11(SW2)
SW_VSTB_3V3_PLL_C: C26.1 R9.1
USB_VCC5P0: C7.1 C8.1 C15.1 C16.1 C95.1 C97.1 C107.1 CB13.1 CB14.1 CONN2.1 CONN20.13 D1.A L1.2 R17.2 U5.10(BIAS)
USB_VCC5P0_BODE: C43.1 R16.2 R17.1
USB_VCC5P0_VIN: C27.1 C28.1 C30.1 LB1.2 U2.2(IN)
VEN_CPLD_VDD1P8: CONN19.6 R65.2
VEN_FPGA_1V2: CONN19.1 R57.2
VEN_FPGA_2V5: CONN19.8 R74.2
VEN_MANG_1P2: CONN19.3 RB24.2
VEN_USB_VCC5P0: CONN19.2 R15.2
VMONITOR_3V3: C17.1 C18.1 C23.1 C38.1 C39.1 C40.1 C108.2 C116.2 C117.1 CB5.1 CB6.1 CB7.1 CONN4.1 CONN20.7 CONN20.19 L3.2 L4.2 L7.1 L8.1 L9.1 R5.2 R14.2 R19.2 R21.2 R25.2 R26.2 R29.2 R31.2 R32.2 R39.2 R43.2 R47.1 R49.2 R66.1 R67.1 R71.1 R91.2 R92.2 R93.2 R94.2 RB6.2 RB9.2 RB12.2 RB15.2 RB16.1 RB23.1
VMONITOR_3V3_EN: C14.1 R7.2 R8.2 U1.7(EN)
VMONITOR_3V3_PG: CONN1.1 R4.1 U1.6(PG)
VREG5_USB_VCC5P0: C41.1 U2.6(VREG)
VREG5_VSTB_3V3: C6.2 R4.2 U1.3(VREG5)
VSTB_3V3: C59.1 C120.1 C121.2 CONN20.6 CONN20.18 L4.1
VSTB_3V3_BODE: C9.1 R2.2 R5.1 U1.1(VO)
VSTB_3V3_VIN: C19.1 C20.1 C21.1 C22.1 L2.2 R8.1 U1.13(VIN1) U1.14(VIN2)
N52288693: C91.1 D1.C DB2.C U4.10(BIAS)
N55217970: R78.1 R79.1 U7.3(ON)
N55218056: C132.1 U7.1(TIMER)
N55218105: C133.2 R80.2
N55218124: R80.1 R81.1 U7.4(GATE)
N55219000: R83.1 R84.1 U8.3(ON)
N55219084: C135.1 U8.1(TIMER)
N55219133: C136.2 R85.2
N55219143: R85.1 R86.1 U8.4(GATE)
N55250293: CB54.2 RB25.2

Pads without a net: CONNB1 4 5 6 7 8 9 10 23 24; CONNB2 4 5 6 7 8 9 10 23 24; Q8 C1; QB2 C2; U4 2 3 4 13 14 17; U5 2 3 4 13 14 17; U6 2 6 7

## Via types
v1: diameter 0.762, hole 0.381, TOP to BOTTOM, 161 vias
v2: diameter 0.559, hole 0.305, TOP to BOTTOM, 680 vias
v3: diameter 0.508, hole 0.254, TOP to BOTTOM, 25 vias

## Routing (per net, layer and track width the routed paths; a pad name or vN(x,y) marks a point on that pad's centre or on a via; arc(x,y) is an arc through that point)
5VSTB1: length 12.5
  TOP w0.762: CONNB1.11 CONNB1.12 CONNB1.14 CONNB1.13
  BOTTOM w0.127: CONNB1.13 28.2,8.86 27.64,9.43 27.64,14.94 27.97,15.27 v1(27.97,15.44)
5VSTB2: length 11.1
  TOP w0.762: CONNB2.13 CONNB2.14 CONNB2.12 CONNB2.11
  BOTTOM w0.127: CONNB2.13 91.24,9.53 v1(91.24,14.15)
AGND_FPGA_1V2: length 4.3
  TOP w0.254: U3.5 12.55,23.53 v2(12.38,23.36)
  BOTTOM w0.127: v1(12.23,21.76) 12.33,21.86 RB21.1
  BOTTOM w0.381: R60.1 11.31,23.15 11.3,23.14 ; v2(12.38,23.36) 12.48,23.46 C64.2
GND: length 1386.3
  TOP w0.254: C41.2 71.89,40.23 v2(71.64,39.97)
  TOP w0.305: v3(25.91,34.3) 25.98,34.22 U5.12 ; U4.12 13.87,34.39 v3(13.79,34.47)
  TOP w0.356: v3(36.69,36.7) 35.71,35.72 U6.4 33.69,35.72 33.45,35.48 R76.1
  TOP w0.381: C90.2 v2(10.81,28.57) ; v2(32.14,41.5) C123.2 C88.2 ; C20.2 v2(90.82,38.7) ; v2(85.28,43.88) 85.28,42.87 85.76,42.38 C30.2 85.89,42.38 86.27,42.77 v2(86.27,43.83) ; v2(101.94,23.36) C78.2 101.22,23.35 C76.2 ; U8.2 v2(73.57,25.75) ; C134.2 50.91,18.48 v2(51.88,17.52) ; CB4.1 v2(72.4,37.48) ; C77.2 98.19,21.21 C75.2 v2(98.16,20.19) ; R63.1 v2(15.5,41.23) ; C15.2 v2(67.47,45.41) ; 52.56,30.55 52.49,30.62 C36.2 ; C1.2 v2(6.06,24.88) ; C111.1 40.12,39.87 v2(39.48,39.24) ; C23.2 v2(82.08,27.55) ; CB8.2 v2(6.49,40.81) ; v2(9.41,22.55) 9.94,22.55 10.18,22.78 C63.2 ; C95.2 28.03,29.19 C97.2 v2(28.86,29.18) ; 21.09,28.26 21.04,28.21 C74.2 20.49,27.73 20.48,27.73 ; C8.2 v2(66.33,47.67) ; C49.2 v2(4.5,40.91) ; C47.2 v2(85.66,48.96) ; C79.2 v2(26.63,23.59) ; C14.2 v2(82.69,28.49) ; C12.2 v2(51.75,15.44) ; C16.2 v2(69.28,43.93) ; R73.1 C113.2 39.84,36.36 v2(39.38,36.82) ; v2(93.91,39.57) 93.89,39.59 C21.2 v2(90.92,39.59) ; C94.2 R68.1 v2(31,32.07) ; C6.1 76.47,32.99 v2(76.38,32.89) ; C18.2 81.04,21.86 v2(80.86,22.04) ; RB19.2 v2(85.86,15.84) ; C50.2 v2(3.49,40.94) ; RB13.1 v2(94.22,12.84) ; v3(25.91,34.3) U5.G1 ; C61.2 v2(93,41.11) ; v2(88.28,15.72) 88.28,15.41 RB20.2 ; R7.1 v2(83.7,28.47) ; C28.2 v2(84.16,36.67) ; U7.2 v2(36.66,32.73) ; DB1.A v2(85.7,51) ; C131.2 v2(32.5,20.67) ; C93.2 v2(9.79,28.55) ; CB3.2 v2(77.02,52.29) ; v2(95.22,17.29) 95.22,17.17 95.61,16.78 QB1.A ; C86.2 v2(10.88,41.38) ; C27.2 v2(83.14,36.7) ; C60.2 v2(85.63,47.92) ; R58.1 10.2,21.79 9.94,21.53 v2(9.46,21.53) ; C92.2 v2(11.82,28.57) ; C68.2 v2(5.5,40.89) ; C10.2 v2(5.04,24.91) ; C89.2 v2(19.59,32.71) ; C33.2 v2(96.53,37.08) ; RB22.1 v2(19.57,33.72) ; C67.2 v2(94.04,41.11) ; CB12.2 v2(25.16,23.67) ; CB5.2 83.91,27.42 v2(84.41,27.93) ; C13.2 v2(52.77,15.38) ; v3(13.79,34.47) U4.G1 ; RB3.1 v2(73.44,37.43) ; C100.2 25.36,40.63 R69.1 v2(26.33,41.34) ; C100.2 v2(25.26,41.24) ; C100.2 C104.2 C102.2 ; C87.2 v2(19.67,36.8) ; R9.2 v2(98.28,34.08) ; C83.2 v2(12.89,41.38) ; C91.2 v2(14.84,28.59) ; C119.2 v2(33.18,41.42) ; C107.2 v2(65.39,49.4) ; C85.2 v2(11.88,41.38) ; v2(87.92,27.98) CB7.2 v2(89.19,26.87) ; C98.1 v2(65.14,43.53) ; C19.2 v2(89.77,38.65) ; C108.1 v2(43.98,37.84) ; C4.2 v2(55.18,15.36) ; CB14.2 18.83,29.83 CB13.2 v2(19.85,30.78) ; C7.2 v2(66.33,50) ; CB6.2 v2(85.91,27.83) ; C11.2 v2(3.01,24.81) ; C3.2 v2(4.03,24.91) ; C66.2 v2(68.49,30.5) ; Q5.A v2(91.58,17.55) ; RB8.1 v2(99.15,36.95) ; C2.2 v2(54.16,15.38)
  G2 w0.635: 14.92,5.3 CONNB1.P1A_5 ; CONNB1.P1A_5 14.2,5.52 ; CONNB1.P1A_5 14.2,6.96 ; CONNB1.P1A_5 15.64,6.96 ; CONNB1.P1A_5 15.64,5.52 ; CONNB1.P1A_5 14.92,7.18 ; CONNB1.P1A_5 13.98,6.24 ; CONNB1.P1A_5 15.86,6.24 ; 81.46,6.96 CONNB2.P1A_3 ; CONNB2.P1A_3 83.11,6.24 ; CONNB2.P1A_3 81.23,6.24 ; CONNB2.P1A_3 82.89,6.96 ; CONNB2.P1A_3 82.89,5.52 ; CONNB2.P1A_3 82.17,7.18 ; CONNB2.P1A_3 82.17,5.3 ; CONNB2.P1A_3 81.46,5.52 ; 21.7,6.96 CONNB1.P1A_2 ; CONNB1.P1A_2 21.7,5.52 ; CONNB1.P1A_2 23.14,5.52 ; CONNB1.P1A_2 22.42,7.18 ; CONNB1.P1A_2 23.14,6.96 ; CONNB1.P1A_2 23.36,6.24 ; CONNB1.P1A_2 22.42,5.3 ; CONNB1.P1A_2 21.48,6.24 ; CONNB1.P2A_5 3.64,5.52 ; CONNB1.P2A_5 2.2,5.52 ; CONNB1.P2A_5 2.92,7.18 ; CONNB1.P2A_5 3.86,6.24 ; CONNB1.P2A_5 2.2,6.96 ; CONNB1.P2A_5 1.98,6.24 ; CONNB1.P2A_5 2.92,5.3 ; CONNB1.P2A_5 3.64,6.96 ; CONNB1.P1A_4 18.14,6.96 ; CONNB1.P1A_4 16.7,5.52 ; CONNB1.P1A_4 16.48,6.24 ; CONNB1.P1A_4 17.42,5.3 ; CONNB1.P1A_4 17.42,7.18 ; CONNB1.P1A_4 18.14,5.52 ; CONNB1.P1A_4 16.7,6.96 ; CONNB1.P1A_4 18.36,6.24 ; 18.98,6.24 CONNB1.P1A_3 ; CONNB1.P1A_3 19.92,7.18 ; CONNB1.P1A_3 20.64,5.52 ; CONNB1.P1A_3 19.2,6.96 ; CONNB1.P1A_3 20.86,6.24 ; CONNB1.P1A_3 19.2,5.52 ; CONNB1.P1A_3 19.92,5.3 ; CONNB1.P1A_3 20.64,6.96 ; 76.46,6.96 CONNB2.P1A_5 ; CONNB2.P1A_5 77.89,5.52 ; CONNB2.P1A_5 78.11,6.24 ; CONNB2.P1A_5 76.46,5.52 ; CONNB2.P1A_5 77.17,5.3 ; CONNB2.P1A_5 77.89,6.96 ; CONNB2.P1A_5 76.23,6.24 ; CONNB2.P1A_5 77.17,7.18 ; 83.95,6.96 CONNB2.P1A_2 ; CONNB2.P1A_2 85.39,5.52 ; CONNB2.P1A_2 84.67,5.3 ; CONNB2.P1A_2 83.95,5.52 ; CONNB2.P1A_2 85.39,6.96 ; CONNB2.P1A_2 83.73,6.24 ; CONNB2.P1A_2 84.67,7.18 ; CONNB2.P1A_2 85.61,6.24 ; CONNB1.P2A_3 8.64,6.96 ; CONNB1.P2A_3 7.2,5.52 ; CONNB1.P2A_3 7.92,7.18 ; CONNB1.P2A_3 6.98,6.24 ; CONNB1.P2A_3 7.92,5.3 ; CONNB1.P2A_3 8.86,6.24 ; CONNB1.P2A_3 7.2,6.96 ; CONNB1.P2A_3 8.64,5.52 ; CONNB2.P1A_4 79.67,7.18 ; CONNB2.P1A_4 78.95,5.52 ; CONNB2.P1A_4 78.73,6.24 ; CONNB2.P1A_4 78.95,6.96 ; CONNB2.P1A_4 80.39,5.52 ; CONNB2.P1A_4 79.67,5.3 ; CONNB2.P1A_4 80.39,6.96 ; CONNB2.P1A_4 80.61,6.24 ; 24.2,6.96 CONNB1.P1A_1 ; CONNB1.P1A_1 24.92,7.18 ; CONNB1.P1A_1 25.64,5.52 ; CONNB1.P1A_1 23.98,6.24 ; CONNB1.P1A_1 24.92,5.3 ; CONNB1.P1A_1 25.64,6.96 ; CONNB1.P1A_1 25.86,6.24 ; CONNB1.P1A_1 24.2,5.52 ; 9.48,6.24 CONNB1.P2A_2 ; CONNB1.P2A_2 11.14,6.96 ; CONNB1.P2A_2 10.42,7.18 ; CONNB1.P2A_2 11.14,5.52 ; CONNB1.P2A_2 10.42,5.3 ; CONNB1.P2A_2 9.7,5.52 ; CONNB1.P2A_2 9.7,6.96 ; CONNB1.P2A_2 11.36,6.24 ; CONNB2.P2A_1 75.89,5.52 ; CONNB2.P2A_1 74.46,5.52 ; CONNB2.P2A_1 74.23,6.24 ; CONNB2.P2A_1 75.89,6.96 ; CONNB2.P2A_1 74.46,6.96 ; CONNB2.P2A_1 75.17,7.18 ; CONNB2.P2A_1 76.11,6.24 ; CONNB2.P2A_1 75.17,5.3 ; 64.23,6.24 CONNB2.P2A_5 ; CONNB2.P2A_5 65.89,5.52 ; CONNB2.P2A_5 66.11,6.24 ; CONNB2.P2A_5 65.17,5.3 ; CONNB2.P2A_5 64.45,6.96 ; CONNB2.P2A_5 65.89,6.96 ; CONNB2.P2A_5 64.45,5.52 ; CONNB2.P2A_5 65.17,7.18 ; 87.17,5.3 CONNB2.P1A_1 ; CONNB2.P1A_1 86.23,6.24 ; CONNB2.P1A_1 87.89,6.96 ; CONNB2.P1A_1 87.17,7.18 ; CONNB2.P1A_1 86.45,5.52 ; CONNB2.P1A_1 86.45,6.96 ; CONNB2.P1A_1 88.11,6.24 ; CONNB2.P1A_1 87.89,5.52 ; CONNB2.P2A_3 70.89,5.52 ; CONNB2.P2A_3 70.17,5.3 ; CONNB2.P2A_3 70.17,7.18 ; CONNB2.P2A_3 69.45,6.96 ; CONNB2.P2A_3 69.23,6.24 ; CONNB2.P2A_3 71.11,6.24 ; CONNB2.P2A_3 70.89,6.96 ; CONNB2.P2A_3 69.45,5.52 ; 71.95,5.52 CONNB2.P2A_2 ; CONNB2.P2A_2 71.95,6.96 ; CONNB2.P2A_2 72.67,7.18 ; CONNB2.P2A_2 71.73,6.24 ; CONNB2.P2A_2 73.39,5.52 ; CONNB2.P2A_2 73.61,6.24 ; CONNB2.P2A_2 72.67,5.3 ; CONNB2.P2A_2 73.39,6.96 ; 66.95,5.52 CONNB2.P2A_4 ; CONNB2.P2A_4 68.39,6.96 ; CONNB2.P2A_4 68.39,5.52 ; CONNB2.P2A_4 68.61,6.24 ; CONNB2.P2A_4 67.67,5.3 ; CONNB2.P2A_4 67.67,7.18 ; CONNB2.P2A_4 66.95,6.96 ; CONNB2.P2A_4 66.73,6.24 ; 11.98,6.24 CONNB1.P2A_1 ; CONNB1.P2A_1 12.2,6.96 ; CONNB1.P2A_1 13.86,6.24 ; CONNB1.P2A_1 12.92,5.3 ; CONNB1.P2A_1 13.64,6.96 ; CONNB1.P2A_1 13.64,5.52 ; CONNB1.P2A_1 12.92,7.18 ; CONNB1.P2A_1 12.2,5.52 ; CONNB1.P2A_4 5.42,7.18 ; CONNB1.P2A_4 4.48,6.24 ; CONNB1.P2A_4 5.42,5.3 ; CONNB1.P2A_4 4.7,6.96 ; CONNB1.P2A_4 6.36,6.24 ; CONNB1.P2A_4 6.14,6.96 ; CONNB1.P2A_4 6.14,5.52 ; CONNB1.P2A_4 4.7,5.52
  G2 w0.762: 55.82,49.89 CONN20.14 ; CONN20.14 57.81,51.87 ; CONN20.14 56.81,52.21 ; CONN20.14 55.82,51.87 ; CONN20.14 55.48,50.88 ; CONN20.14 57.81,49.89 ; CONN20.14 56.81,49.55 ; CONN20.14 58.15,50.88 ; CONN20.2 57.81,46.37 ; CONN20.2 58.15,45.38 ; CONN20.2 55.82,44.39 ; CONN20.2 55.48,45.38 ; CONN20.2 55.82,46.37 ; CONN20.2 56.81,44.05 ; CONN20.2 57.81,44.39 ; CONN20.2 56.81,46.71 ; 18.02,44.39 CONN20.11 ; CONN20.11 19.01,46.71 ; CONN20.11 18.02,46.37 ; CONN20.11 20.35,45.38 ; CONN20.11 20.01,44.39 ; CONN20.11 19.01,44.05 ; CONN20.11 17.68,45.38 ; CONN20.11 20.01,46.37 ; 13.82,49.89 CONN20.24 ; CONN20.24 15.81,51.87 ; CONN20.24 16.15,50.88 ; CONN20.24 15.81,49.89 ; CONN20.24 13.48,50.88 ; CONN20.24 14.81,52.21 ; CONN20.24 13.82,51.87 ; CONN20.24 14.81,49.55 ; CONN20.23 20.35,50.88 ; CONN20.23 18.02,51.87 ; CONN20.23 18.02,49.89 ; CONN20.23 20.01,49.89 ; CONN20.23 19.01,52.21 ; CONN20.23 20.01,51.87 ; CONN20.23 17.68,50.88 ; CONN20.23 19.01,49.55 ; 44.21,49.55 CONN20.17 ; CONN20.17 44.21,52.21 ; CONN20.17 45.21,49.89 ; CONN20.17 42.88,50.88 ; CONN20.17 45.55,50.88 ; CONN20.17 43.22,51.87 ; CONN20.17 45.21,51.87 ; CONN20.17 43.22,49.89 ; 14.81,44.05 CONN20.12 ; CONN20.12 16.15,45.38 ; CONN20.12 13.48,45.38 ; CONN20.12 14.81,46.71 ; CONN20.12 15.81,46.37 ; CONN20.12 13.82,46.37 ; CONN20.12 15.81,44.39 ; CONN20.12 13.82,44.39 ; 30.62,49.89 CONN20.20 ; CONN20.20 32.61,49.89 ; CONN20.20 32.61,51.87 ; CONN20.20 31.61,49.55 ; CONN20.20 30.28,50.88 ; CONN20.20 32.95,50.88 ; CONN20.20 31.61,52.21 ; CONN20.20 30.62,51.87 ; 31.61,44.05 CONN20.8 ; CONN20.8 30.28,45.38 ; CONN20.8 31.61,46.71 ; CONN20.8 30.62,46.37 ; CONN20.8 32.61,44.39 ; CONN20.8 32.95,45.38 ; CONN20.8 30.62,44.39 ; CONN20.8 32.61,46.37 ; CONN20.5 45.55,45.38 ; CONN20.5 43.22,44.39 ; CONN20.5 43.22,46.37 ; CONN20.5 42.88,45.38 ; CONN20.5 45.21,44.39 ; CONN20.5 44.21,44.05 ; CONN20.5 44.21,46.71 ; CONN20.5 45.21,46.37
  V4 w0.635: CONNB1.P2A_4 5.42,7.18 ; CONNB1.P2A_4 6.14,5.52 ; CONNB1.P2A_4 4.7,5.52 ; CONNB1.P2A_4 5.42,5.3 ; CONNB1.P2A_4 4.7,6.96 ; CONNB1.P2A_4 6.36,6.24 ; CONNB1.P2A_4 6.14,6.96 ; CONNB1.P2A_4 4.48,6.24 ; CONNB2.P2A_1 75.89,6.96 ; CONNB2.P2A_1 76.11,6.24 ; CONNB2.P2A_1 74.23,6.24 ; CONNB2.P2A_1 74.46,5.52 ; CONNB2.P2A_1 75.17,7.18 ; CONNB2.P2A_1 75.89,5.52 ; CONNB2.P2A_1 75.17,5.3 ; CONNB2.P2A_1 74.46,6.96 ; 76.46,6.96 CONNB2.P1A_5 ; CONNB2.P1A_5 78.11,6.24 ; CONNB2.P1A_5 76.23,6.24 ; CONNB2.P1A_5 77.17,5.3 ; CONNB2.P1A_5 77.89,6.96 ; CONNB2.P1A_5 77.89,5.52 ; CONNB2.P1A_5 76.46,5.52 ; CONNB2.P1A_5 77.17,7.18 ; 22.42,5.3 CONNB1.P1A_2 ; CONNB1.P1A_2 21.7,5.52 ; CONNB1.P1A_2 21.7,6.96 ; CONNB1.P1A_2 21.48,6.24 ; CONNB1.P1A_2 23.36,6.24 ; CONNB1.P1A_2 23.14,5.52 ; CONNB1.P1A_2 23.14,6.96 ; CONNB1.P1A_2 22.42,7.18 ; 12.2,5.52 CONNB1.P2A_1 ; CONNB1.P2A_1 11.98,6.24 ; CONNB1.P2A_1 13.86,6.24 ; CONNB1.P2A_1 12.2,6.96 ; CONNB1.P2A_1 12.92,5.3 ; CONNB1.P2A_1 13.64,5.52 ; CONNB1.P2A_1 13.64,6.96 ; CONNB1.P2A_1 12.92,7.18 ; 16.7,5.52 CONNB1.P1A_4 ; CONNB1.P1A_4 16.7,6.96 ; CONNB1.P1A_4 16.48,6.24 ; CONNB1.P1A_4 18.36,6.24 ; CONNB1.P1A_4 18.14,5.52 ; CONNB1.P1A_4 17.42,7.18 ; CONNB1.P1A_4 18.14,6.96 ; CONNB1.P1A_4 17.42,5.3 ; CONNB1.P2A_2 10.42,7.18 ; CONNB1.P2A_2 11.14,5.52 ; CONNB1.P2A_2 9.48,6.24 ; CONNB1.P2A_2 11.14,6.96 ; CONNB1.P2A_2 9.7,6.96 ; CONNB1.P2A_2 9.7,5.52 ; CONNB1.P2A_2 10.42,5.3 ; CONNB1.P2A_2 11.36,6.24 ; CONNB1.P2A_3 8.64,5.52 ; CONNB1.P2A_3 7.92,5.3 ; CONNB1.P2A_3 8.86,6.24 ; CONNB1.P2A_3 6.98,6.24 ; CONNB1.P2A_3 7.2,6.96 ; CONNB1.P2A_3 7.92,7.18 ; CONNB1.P2A_3 8.64,6.96 ; CONNB1.P2A_3 7.2,5.52 ; 2.92,5.3 CONNB1.P2A_5 ; CONNB1.P2A_5 1.98,6.24 ; CONNB1.P2A_5 3.64,6.96 ; CONNB1.P2A_5 3.86,6.24 ; CONNB1.P2A_5 2.92,7.18 ; CONNB1.P2A_5 3.64,5.52 ; CONNB1.P2A_5 2.2,5.52 ; CONNB1.P2A_5 2.2,6.96 ; CONNB2.P2A_5 65.17,7.18 ; CONNB2.P2A_5 64.45,6.96 ; CONNB2.P2A_5 66.11,6.24 ; CONNB2.P2A_5 64.45,5.52 ; CONNB2.P2A_5 64.23,6.24 ; CONNB2.P2A_5 65.89,6.96 ; CONNB2.P2A_5 65.89,5.52 ; CONNB2.P2A_5 65.17,5.3 ; 83.73,6.24 CONNB2.P1A_2 ; CONNB2.P1A_2 83.95,5.52 ; CONNB2.P1A_2 85.61,6.24 ; CONNB2.P1A_2 84.67,5.3 ; CONNB2.P1A_2 84.67,7.18 ; CONNB2.P1A_2 85.39,6.96 ; CONNB2.P1A_2 83.95,6.96 ; CONNB2.P1A_2 85.39,5.52 ; 78.95,6.96 CONNB2.P1A_4 ; CONNB2.P1A_4 80.61,6.24 ; CONNB2.P1A_4 79.67,5.3 ; CONNB2.P1A_4 80.39,6.96 ; CONNB2.P1A_4 78.73,6.24 ; CONNB2.P1A_4 78.95,5.52 ; CONNB2.P1A_4 80.39,5.52 ; CONNB2.P1A_4 79.67,7.18 ; CONNB1.P1A_5 14.92,7.18 ; CONNB1.P1A_5 14.92,5.3 ; CONNB1.P1A_5 13.98,6.24 ; CONNB1.P1A_5 15.64,5.52 ; CONNB1.P1A_5 15.86,6.24 ; CONNB1.P1A_5 14.2,5.52 ; CONNB1.P1A_5 15.64,6.96 ; CONNB1.P1A_5 14.2,6.96 ; 24.2,6.96 CONNB1.P1A_1 ; CONNB1.P1A_1 24.92,5.3 ; CONNB1.P1A_1 25.64,6.96 ; CONNB1.P1A_1 23.98,6.24 ; CONNB1.P1A_1 24.92,7.18 ; CONNB1.P1A_1 24.2,5.52 ; CONNB1.P1A_1 25.64,5.52 ; CONNB1.P1A_1 25.86,6.24 ; 69.45,5.52 CONNB2.P2A_3 ; CONNB2.P2A_3 70.17,7.18 ; CONNB2.P2A_3 70.17,5.3 ; CONNB2.P2A_3 70.89,5.52 ; CONNB2.P2A_3 69.23,6.24 ; CONNB2.P2A_3 69.45,6.96 ; CONNB2.P2A_3 70.89,6.96 ; CONNB2.P2A_3 71.11,6.24 ; CONNB2.P1A_1 88.11,6.24 ; CONNB2.P1A_1 86.45,6.96 ; CONNB2.P1A_1 86.23,6.24 ; CONNB2.P1A_1 87.89,6.96 ; CONNB2.P1A_1 86.45,5.52 ; CONNB2.P1A_1 87.89,5.52 ; CONNB2.P1A_1 87.17,5.3 ; CONNB2.P1A_1 87.17,7.18 ; CONNB2.P1A_3 83.11,6.24 ; CONNB2.P1A_3 82.89,5.52 ; CONNB2.P1A_3 82.17,7.18 ; CONNB2.P1A_3 82.89,6.96 ; CONNB2.P1A_3 81.46,5.52 ; CONNB2.P1A_3 82.17,5.3 ; CONNB2.P1A_3 81.46,6.96 ; CONNB2.P1A_3 81.23,6.24 ; CONNB1.P1A_3 20.64,6.96 ; CONNB1.P1A_3 19.92,5.3 ; CONNB1.P1A_3 19.2,6.96 ; CONNB1.P1A_3 18.98,6.24 ; CONNB1.P1A_3 19.92,7.18 ; CONNB1.P1A_3 19.2,5.52 ; CONNB1.P1A_3 20.64,5.52 ; CONNB1.P1A_3 20.86,6.24 ; 66.95,6.96 CONNB2.P2A_4 ; CONNB2.P2A_4 66.73,6.24 ; CONNB2.P2A_4 67.67,5.3 ; CONNB2.P2A_4 67.67,7.18 ; CONNB2.P2A_4 68.39,5.52 ; CONNB2.P2A_4 68.39,6.96 ; CONNB2.P2A_4 66.95,5.52 ; CONNB2.P2A_4 68.61,6.24 ; CONNB2.P2A_2 72.67,7.18 ; CONNB2.P2A_2 71.95,5.52 ; CONNB2.P2A_2 71.95,6.96 ; CONNB2.P2A_2 73.39,6.96 ; CONNB2.P2A_2 73.39,5.52 ; CONNB2.P2A_2 71.73,6.24 ; CONNB2.P2A_2 72.67,5.3 ; CONNB2.P2A_2 73.61,6.24
  V5 w0.635: CONNB2.P1A_5 77.17,7.18 ; CONNB2.P1A_5 77.89,6.96 ; CONNB2.P1A_5 77.17,5.3 ; CONNB2.P1A_5 76.46,6.96 ; CONNB2.P1A_5 76.46,5.52 ; CONNB2.P1A_5 76.23,6.24 ; CONNB2.P1A_5 77.89,5.52 ; CONNB2.P1A_5 78.11,6.24 ; CONNB2.P2A_5 66.11,6.24 ; CONNB2.P2A_5 64.45,5.52 ; CONNB2.P2A_5 64.45,6.96 ; CONNB2.P2A_5 65.89,5.52 ; CONNB2.P2A_5 65.17,5.3 ; CONNB2.P2A_5 65.89,6.96 ; CONNB2.P2A_5 64.23,6.24 ; CONNB2.P2A_5 65.17,7.18 ; 12.2,5.52 CONNB1.P2A_1 ; CONNB1.P2A_1 12.92,7.18 ; CONNB1.P2A_1 13.64,6.96 ; CONNB1.P2A_1 11.98,6.24 ; CONNB1.P2A_1 12.2,6.96 ; CONNB1.P2A_1 12.92,5.3 ; CONNB1.P2A_1 13.64,5.52 ; CONNB1.P2A_1 13.86,6.24 ; CONNB1.P1A_2 23.14,6.96 ; CONNB1.P1A_2 21.7,5.52 ; CONNB1.P1A_2 23.14,5.52 ; CONNB1.P1A_2 21.48,6.24 ; CONNB1.P1A_2 22.42,7.18 ; CONNB1.P1A_2 21.7,6.96 ; CONNB1.P1A_2 22.42,5.3 ; CONNB1.P1A_2 23.36,6.24 ; 83.73,6.24 CONNB2.P1A_2 ; CONNB2.P1A_2 84.67,7.18 ; CONNB2.P1A_2 83.95,6.96 ; CONNB2.P1A_2 85.39,5.52 ; CONNB2.P1A_2 85.39,6.96 ; CONNB2.P1A_2 85.61,6.24 ; CONNB2.P1A_2 84.67,5.3 ; CONNB2.P1A_2 83.95,5.52 ; CONNB1.P1A_4 17.42,7.18 ; CONNB1.P1A_4 16.7,5.52 ; CONNB1.P1A_4 18.36,6.24 ; CONNB1.P1A_4 18.14,5.52 ; CONNB1.P1A_4 17.42,5.3 ; CONNB1.P1A_4 16.7,6.96 ; CONNB1.P1A_4 16.48,6.24 ; CONNB1.P1A_4 18.14,6.96 ; 10.42,5.3 CONNB1.P2A_2 ; CONNB1.P2A_2 10.42,7.18 ; CONNB1.P2A_2 9.7,5.52 ; CONNB1.P2A_2 9.48,6.24 ; CONNB1.P2A_2 11.36,6.24 ; CONNB1.P2A_2 11.14,6.96 ; CONNB1.P2A_2 11.14,5.52 ; CONNB1.P2A_2 9.7,6.96 ; CONNB1.P1A_5 15.64,6.96 ; CONNB1.P1A_5 14.92,5.3 ; CONNB1.P1A_5 13.98,6.24 ; CONNB1.P1A_5 14.2,6.96 ; CONNB1.P1A_5 14.92,7.18 ; CONNB1.P1A_5 15.64,5.52 ; CONNB1.P1A_5 15.86,6.24 ; CONNB1.P1A_5 14.2,5.52 ; 74.46,6.96 CONNB2.P2A_1 ; CONNB2.P2A_1 75.89,5.52 ; CONNB2.P2A_1 74.46,5.52 ; CONNB2.P2A_1 74.23,6.24 ; CONNB2.P2A_1 75.17,7.18 ; CONNB2.P2A_1 75.17,5.3 ; CONNB2.P2A_1 75.89,6.96 ; CONNB2.P2A_1 76.11,6.24 ; 67.67,5.3 CONNB2.P2A_4 ; CONNB2.P2A_4 66.95,5.52 ; CONNB2.P2A_4 66.73,6.24 ; CONNB2.P2A_4 66.95,6.96 ; CONNB2.P2A_4 68.39,6.96 ; CONNB2.P2A_4 68.39,5.52 ; CONNB2.P2A_4 67.67,7.18 ; CONNB2.P2A_4 68.61,6.24 ; CONNB1.P2A_3 8.64,5.52 ; CONNB1.P2A_3 7.2,6.96 ; CONNB1.P2A_3 7.92,5.3 ; CONNB1.P2A_3 7.2,5.52 ; CONNB1.P2A_3 6.98,6.24 ; CONNB1.P2A_3 8.86,6.24 ; CONNB1.P2A_3 7.92,7.18 ; CONNB1.P2A_3 8.64,6.96 ; 4.7,5.52 CONNB1.P2A_4 ; CONNB1.P2A_4 4.48,6.24 ; CONNB1.P2A_4 5.42,5.3 ; CONNB1.P2A_4 6.14,5.52 ; CONNB1.P2A_4 4.7,6.96 ; CONNB1.P2A_4 5.42,7.18 ; CONNB1.P2A_4 6.36,6.24 ; CONNB1.P2A_4 6.14,6.96 ; CONNB2.P2A_2 73.39,6.96 ; CONNB2.P2A_2 71.73,6.24 ; CONNB2.P2A_2 73.39,5.52 ; CONNB2.P2A_2 71.95,6.96 ; CONNB2.P2A_2 71.95,5.52 ; CONNB2.P2A_2 72.67,7.18 ; CONNB2.P2A_2 72.67,5.3 ; CONNB2.P2A_2 73.61,6.24 ; CONNB2.P1A_4 79.67,7.18 ; CONNB2.P1A_4 80.39,5.52 ; CONNB2.P1A_4 78.95,5.52 ; CONNB2.P1A_4 78.95,6.96 ; CONNB2.P1A_4 80.61,6.24 ; CONNB2.P1A_4 79.67,5.3 ; CONNB2.P1A_4 80.39,6.96 ; CONNB2.P1A_4 78.73,6.24 ; CONNB1.P1A_1 24.92,7.18 ; CONNB1.P1A_1 25.64,6.96 ; CONNB1.P1A_1 23.98,6.24 ; CONNB1.P1A_1 24.2,5.52 ; CONNB1.P1A_1 25.64,5.52 ; CONNB1.P1A_1 24.92,5.3 ; CONNB1.P1A_1 25.86,6.24 ; CONNB1.P1A_1 24.2,6.96 ; 87.17,5.3 CONNB2.P1A_1 ; CONNB2.P1A_1 87.89,5.52 ; CONNB2.P1A_1 87.17,7.18 ; CONNB2.P1A_1 88.11,6.24 ; CONNB2.P1A_1 86.45,5.52 ; CONNB2.P1A_1 86.23,6.24 ; CONNB2.P1A_1 86.45,6.96 ; CONNB2.P1A_1 87.89,6.96 ; CONNB2.P1A_3 82.89,5.52 ; CONNB2.P1A_3 82.89,6.96 ; CONNB2.P1A_3 81.46,5.52 ; CONNB2.P1A_3 81.23,6.24 ; CONNB2.P1A_3 83.11,6.24 ; CONNB2.P1A_3 81.46,6.96 ; CONNB2.P1A_3 82.17,5.3 ; CONNB2.P1A_3 82.17,7.18 ; CONNB1.P2A_5 2.92,7.18 ; CONNB1.P2A_5 1.98,6.24 ; CONNB1.P2A_5 2.2,5.52 ; CONNB1.P2A_5 3.64,5.52 ; CONNB1.P2A_5 3.64,6.96 ; CONNB1.P2A_5 2.92,5.3 ; CONNB1.P2A_5 2.2,6.96 ; CONNB1.P2A_5 3.86,6.24 ; 70.17,5.3 CONNB2.P2A_3 ; CONNB2.P2A_3 70.17,7.18 ; CONNB2.P2A_3 69.45,5.52 ; CONNB2.P2A_3 70.89,6.96 ; CONNB2.P2A_3 69.23,6.24 ; CONNB2.P2A_3 70.89,5.52 ; CONNB2.P2A_3 69.45,6.96 ; CONNB2.P2A_3 71.11,6.24 ; CONNB1.P1A_3 19.92,7.18 ; CONNB1.P1A_3 20.86,6.24 ; CONNB1.P1A_3 19.2,6.96 ; CONNB1.P1A_3 18.98,6.24 ; CONNB1.P1A_3 20.64,5.52 ; CONNB1.P1A_3 19.92,5.3 ; CONNB1.P1A_3 19.2,5.52 ; CONNB1.P1A_3 20.64,6.96
  V5 w0.762: 44.21,49.55 CONN20.17 ; CONN20.17 42.88,50.88 ; CONN20.17 45.21,49.89 ; CONN20.17 43.22,49.89 ; CONN20.17 44.21,52.21 ; CONN20.17 45.21,51.87 ; CONN20.17 43.22,51.87 ; CONN20.23 20.01,51.87 ; CONN20.23 20.01,49.89 ; CONN20.23 17.68,50.88 ; CONN20.23 19.01,49.55 ; CONN20.23 18.02,51.87 ; CONN20.23 19.01,52.21 ; CONN20.23 20.35,50.88 ; CONN20.23 18.02,49.89 ; CONN20.12 14.81,46.71 ; CONN20.12 16.15,45.38 ; CONN20.12 15.81,44.39 ; CONN20.12 15.81,46.37 ; CONN20.12 13.82,44.39 ; CONN20.12 13.82,46.37 ; CONN20.12 13.48,45.38 ; CONN20.12 14.81,44.05 ; CONN20.14 56.81,52.21 ; CONN20.14 57.81,49.89 ; CONN20.14 57.81,51.87 ; CONN20.14 55.48,50.88 ; CONN20.14 55.82,51.87 ; CONN20.14 56.81,49.55 ; CONN20.14 58.15,50.88 ; CONN20.14 55.82,49.89 ; 30.28,50.88 CONN20.20 ; CONN20.20 30.62,51.87 ; CONN20.20 30.62,49.89 ; CONN20.20 31.61,49.55 ; CONN20.20 32.95,50.88 ; CONN20.20 32.61,51.87 ; CONN20.20 32.61,49.89 ; CONN20.20 31.61,52.21 ; 17.68,45.38 CONN20.11 ; CONN20.11 19.01,46.71 ; CONN20.11 20.01,46.37 ; CONN20.11 20.01,44.39 ; CONN20.11 18.02,44.39 ; CONN20.11 18.02,46.37 ; CONN20.11 20.35,45.38 ; CONN20.11 19.01,44.05 ; CONN20.2 56.81,46.71 ; CONN20.2 56.81,44.05 ; CONN20.2 55.48,45.38 ; CONN20.2 55.82,44.39 ; CONN20.2 57.81,44.39 ; CONN20.2 55.82,46.37 ; CONN20.2 57.81,46.37 ; CONN20.8 32.61,44.39 ; CONN20.8 32.61,46.37 ; CONN20.8 32.95,45.38 ; CONN20.8 31.61,44.05 ; CONN20.8 31.61,46.71 ; 14.81,49.55 CONN20.24 ; CONN20.24 16.15,50.88 ; CONN20.24 13.82,51.87 ; CONN20.24 14.81,52.21 ; CONN20.24 15.81,51.87 ; CONN20.24 13.82,49.89 ; CONN20.24 15.81,49.89 ; CONN20.24 13.48,50.88 ; 42.88,45.38 CONN20.5 ; CONN20.5 43.22,44.39 ; CONN20.5 43.22,46.37 ; CONN20.5 44.21,44.05 ; CONN20.5 44.21,46.71 ; CONN20.5 45.21,46.37 ; CONN20.5 45.21,44.39
  V6 w0.635: 23.98,6.24 CONNB1.P1A_1 ; CONNB1.P1A_1 24.2,5.52 ; CONNB1.P1A_1 25.86,6.24 ; CONNB1.P1A_1 24.2,6.96 ; CONNB1.P1A_1 24.92,5.3 ; CONNB1.P1A_1 25.64,6.96 ; CONNB1.P1A_1 24.92,7.18 ; CONNB1.P1A_1 25.64,5.52 ; CONNB2.P1A_4 79.67,7.18 ; CONNB2.P1A_4 78.95,6.96 ; CONNB2.P1A_4 78.73,6.24 ; CONNB2.P1A_4 80.39,6.96 ; CONNB2.P1A_4 80.61,6.24 ; CONNB2.P1A_4 79.67,5.3 ; CONNB2.P1A_4 80.39,5.52 ; CONNB2.P1A_4 78.95,5.52 ; 9.48,6.24 CONNB1.P2A_2 ; CONNB1.P2A_2 11.36,6.24 ; CONNB1.P2A_2 10.42,7.18 ; CONNB1.P2A_2 9.7,6.96 ; CONNB1.P2A_2 11.14,6.96 ; CONNB1.P2A_2 11.14,5.52 ; CONNB1.P2A_2 10.42,5.3 ; CONNB1.P2A_2 9.7,5.52 ; CONNB1.P2A_5 3.64,6.96 ; CONNB1.P2A_5 3.64,5.52 ; CONNB1.P2A_5 2.2,6.96 ; CONNB1.P2A_5 1.98,6.24 ; CONNB1.P2A_5 2.92,5.3 ; CONNB1.P2A_5 2.2,5.52 ; CONNB1.P2A_5 3.86,6.24 ; CONNB1.P2A_5 2.92,7.18 ; 4.7,5.52 CONNB1.P2A_4 ; CONNB1.P2A_4 6.14,5.52 ; CONNB1.P2A_4 5.42,7.18 ; CONNB1.P2A_4 5.42,5.3 ; CONNB1.P2A_4 4.7,6.96 ; CONNB1.P2A_4 6.36,6.24 ; CONNB1.P2A_4 6.14,6.96 ; CONNB1.P2A_4 4.48,6.24 ; CONNB1.P1A_4 18.14,6.96 ; CONNB1.P1A_4 17.42,5.3 ; CONNB1.P1A_4 16.7,5.52 ; CONNB1.P1A_4 16.48,6.24 ; CONNB1.P1A_4 18.14,5.52 ; CONNB1.P1A_4 18.36,6.24 ; CONNB1.P1A_4 17.42,7.18 ; CONNB1.P1A_4 16.7,6.96 ; 74.46,5.52 CONNB2.P2A_1 ; CONNB2.P2A_1 75.89,6.96 ; CONNB2.P2A_1 75.89,5.52 ; CONNB2.P2A_1 74.23,6.24 ; CONNB2.P2A_1 74.46,6.96 ; CONNB2.P2A_1 75.17,7.18 ; CONNB2.P2A_1 76.11,6.24 ; CONNB2.P2A_1 75.17,5.3 ; 81.23,6.24 CONNB2.P1A_3 ; CONNB2.P1A_3 83.11,6.24 ; CONNB2.P1A_3 82.17,5.3 ; CONNB2.P1A_3 81.46,5.52 ; CONNB2.P1A_3 82.17,7.18 ; CONNB2.P1A_3 82.89,5.52 ; CONNB2.P1A_3 82.89,6.96 ; CONNB2.P1A_3 81.46,6.96 ; 21.48,6.24 CONNB1.P1A_2 ; CONNB1.P1A_2 23.14,5.52 ; CONNB1.P1A_2 22.42,7.18 ; CONNB1.P1A_2 21.7,6.96 ; CONNB1.P1A_2 21.7,5.52 ; CONNB1.P1A_2 22.42,5.3 ; CONNB1.P1A_2 23.14,6.96 ; CONNB1.P1A_2 23.36,6.24 ; CONNB1.P1A_5 15.86,6.24 ; CONNB1.P1A_5 13.98,6.24 ; CONNB1.P1A_5 14.2,6.96 ; CONNB1.P1A_5 14.2,5.52 ; CONNB1.P1A_5 15.64,5.52 ; CONNB1.P1A_5 14.92,5.3 ; CONNB1.P1A_5 14.92,7.18 ; CONNB1.P1A_5 15.64,6.96 ; 12.92,5.3 CONNB1.P2A_1 ; CONNB1.P2A_1 11.98,6.24 ; CONNB1.P2A_1 13.64,6.96 ; CONNB1.P2A_1 12.2,5.52 ; CONNB1.P2A_1 12.2,6.96 ; CONNB1.P2A_1 13.64,5.52 ; CONNB1.P2A_1 12.92,7.18 ; CONNB1.P2A_1 13.86,6.24 ; 83.95,5.52 CONNB2.P1A_2 ; CONNB2.P1A_2 83.73,6.24 ; CONNB2.P1A_2 85.39,5.52 ; CONNB2.P1A_2 85.61,6.24 ; CONNB2.P1A_2 84.67,7.18 ; CONNB2.P1A_2 85.39,6.96 ; CONNB2.P1A_2 84.67,5.3 ; CONNB2.P1A_2 83.95,6.96 ; 7.2,5.52 CONNB1.P2A_3 ; CONNB1.P2A_3 7.92,5.3 ; CONNB1.P2A_3 6.98,6.24 ; CONNB1.P2A_3 7.2,6.96 ; CONNB1.P2A_3 8.64,6.96 ; CONNB1.P2A_3 7.92,7.18 ; CONNB1.P2A_3 8.86,6.24 ; CONNB1.P2A_3 8.64,5.52 ; 19.2,6.96 CONNB1.P1A_3 ; CONNB1.P1A_3 19.92,7.18 ; CONNB1.P1A_3 20.64,6.96 ; CONNB1.P1A_3 20.86,6.24 ; CONNB1.P1A_3 19.2,5.52 ; CONNB1.P1A_3 18.98,6.24 ; CONNB1.P1A_3 19.92,5.3 ; CONNB1.P1A_3 20.64,5.52 ; 86.23,6.24 CONNB2.P1A_1 ; CONNB2.P1A_1 87.89,5.52 ; CONNB2.P1A_1 87.89,6.96 ; CONNB2.P1A_1 87.17,7.18 ; CONNB2.P1A_1 88.11,6.24 ; CONNB2.P1A_1 87.17,5.3 ; CONNB2.P1A_1 86.45,5.52 ; CONNB2.P1A_1 86.45,6.96 ; CONNB2.P2A_4 67.67,7.18 ; CONNB2.P2A_4 66.95,5.52 ; CONNB2.P2A_4 66.95,6.96 ; CONNB2.P2A_4 68.39,5.52 ; CONNB2.P2A_4 68.39,6.96 ; CONNB2.P2A_4 68.61,6.24 ; CONNB2.P2A_4 66.73,6.24 ; CONNB2.P2A_4 67.67,5.3 ; CONNB2.P2A_5 65.89,5.52 ; CONNB2.P2A_5 65.17,5.3 ; CONNB2.P2A_5 64.45,6.96 ; CONNB2.P2A_5 65.17,7.18 ; CONNB2.P2A_5 66.11,6.24 ; CONNB2.P2A_5 64.45,5.52 ; CONNB2.P2A_5 64.23,6.24 ; CONNB2.P2A_5 65.89,6.96 ; 69.45,5.52 CONNB2.P2A_3 ; CONNB2.P2A_3 69.23,6.24 ; CONNB2.P2A_3 71.11,6.24 ; CONNB2.P2A_3 70.89,6.96 ; CONNB2.P2A_3 70.17,7.18 ; CONNB2.P2A_3 69.45,6.96 ; CONNB2.P2A_3 70.89,5.52 ; CONNB2.P2A_3 70.17,5.3 ; 71.95,6.96 CONNB2.P2A_2 ; CONNB2.P2A_2 73.39,5.52 ; CONNB2.P2A_2 73.39,6.96 ; CONNB2.P2A_2 71.73,6.24 ; CONNB2.P2A_2 72.67,7.18 ; CONNB2.P2A_2 72.67,5.3 ; CONNB2.P2A_2 71.95,5.52 ; CONNB2.P2A_2 73.61,6.24 ; 77.17,5.3 CONNB2.P1A_5 ; CONNB2.P1A_5 78.11,6.24 ; CONNB2.P1A_5 77.89,5.52 ; CONNB2.P1A_5 76.46,6.96 ; CONNB2.P1A_5 76.23,6.24 ; CONNB2.P1A_5 76.46,5.52 ; CONNB2.P1A_5 77.89,6.96 ; CONNB2.P1A_5 77.17,7.18
  V6 w0.762: CONN20.11 19.01,46.71 ; CONN20.11 20.35,45.38 ; CONN20.11 20.01,44.39 ; CONN20.11 17.68,45.38 ; CONN20.11 19.01,44.05 ; CONN20.11 18.02,46.37 ; CONN20.11 18.02,44.39 ; CONN20.11 20.01,46.37 ; CONN20.24 15.81,49.89 ; CONN20.24 13.48,50.88 ; CONN20.24 15.81,51.87 ; CONN20.24 14.81,49.55 ; CONN20.24 13.82,49.89 ; CONN20.24 14.81,52.21 ; CONN20.24 13.82,51.87 ; CONN20.24 16.15,50.88 ; 55.82,51.87 CONN20.14 ; CONN20.14 58.15,50.88 ; CONN20.14 56.81,49.55 ; CONN20.14 57.81,51.87 ; CONN20.14 55.48,50.88 ; CONN20.14 57.81,49.89 ; CONN20.14 55.82,49.89 ; CONN20.14 56.81,52.21 ; 30.28,45.38 CONN20.8 ; CONN20.8 30.62,44.39 ; CONN20.8 32.61,44.39 ; CONN20.8 32.61,46.37 ; CONN20.8 32.95,45.38 ; CONN20.8 31.61,46.71 ; CONN20.8 31.61,44.05 ; CONN20.8 30.62,46.37 ; 42.88,50.88 CONN20.17 ; CONN20.17 44.21,52.21 ; CONN20.17 45.21,51.87 ; CONN20.17 44.21,49.55 ; CONN20.17 45.21,49.89 ; CONN20.17 43.22,51.87 ; CONN20.17 43.22,49.89 ; 31.61,49.55 CONN20.20 ; CONN20.20 32.61,51.87 ; CONN20.20 30.28,50.88 ; CONN20.20 32.95,50.88 ; CONN20.20 30.62,51.87 ; CONN20.20 31.61,52.21 ; CONN20.20 30.62,49.89 ; CONN20.20 32.61,49.89 ; 18.02,51.87 CONN20.23 ; CONN20.23 20.01,51.87 ; CONN20.23 18.02,49.89 ; CONN20.23 17.68,50.88 ; CONN20.23 19.01,49.55 ; CONN20.23 20.01,49.89 ; CONN20.23 20.35,50.88 ; CONN20.23 19.01,52.21 ; CONN20.5 45.21,46.37 ; CONN20.5 45.21,44.39 ; CONN20.5 42.88,45.38 ; CONN20.5 44.21,44.05 ; CONN20.5 43.22,44.39 ; CONN20.5 43.22,46.37 ; CONN20.5 44.21,46.71 ; CONN20.12 16.15,45.38 ; CONN20.12 15.81,44.39 ; CONN20.12 13.48,45.38 ; CONN20.12 13.82,44.39 ; CONN20.12 14.81,44.05 ; CONN20.12 14.81,46.71 ; CONN20.12 13.82,46.37 ; CONN20.12 15.81,46.37 ; 55.82,46.37 CONN20.2 ; CONN20.2 56.81,44.05 ; CONN20.2 55.82,44.39 ; CONN20.2 56.81,46.71 ; CONN20.2 57.81,44.39 ; CONN20.2 57.81,46.37 ; CONN20.2 55.48,45.38
  G7 w0.635: CONNB1.P1A_4 17.42,7.18 ; CONNB1.P1A_4 16.7,5.52 ; CONNB1.P1A_4 18.36,6.24 ; CONNB1.P1A_4 16.7,6.96 ; CONNB1.P1A_4 17.42,5.3 ; CONNB1.P1A_4 16.48,6.24 ; CONNB1.P1A_4 18.14,6.96 ; CONNB1.P1A_4 18.14,5.52 ; 71.73,6.24 CONNB2.P2A_2 ; CONNB2.P2A_2 72.67,7.18 ; CONNB2.P2A_2 73.61,6.24 ; CONNB2.P2A_2 73.39,5.52 ; CONNB2.P2A_2 73.39,6.96 ; CONNB2.P2A_2 71.95,6.96 ; CONNB2.P2A_2 71.95,5.52 ; CONNB2.P2A_2 72.67,5.3 ; CONNB2.P2A_1 75.17,7.18 ; CONNB2.P2A_1 75.89,5.52 ; CONNB2.P2A_1 75.89,6.96 ; CONNB2.P2A_1 76.11,6.24 ; CONNB2.P2A_1 74.23,6.24 ; CONNB2.P2A_1 74.46,5.52 ; CONNB2.P2A_1 75.17,5.3 ; CONNB2.P2A_1 74.46,6.96 ; 2.2,6.96 CONNB1.P2A_5 ; CONNB1.P2A_5 1.98,6.24 ; CONNB1.P2A_5 3.64,6.96 ; CONNB1.P2A_5 3.86,6.24 ; CONNB1.P2A_5 2.92,7.18 ; CONNB1.P2A_5 2.92,5.3 ; CONNB1.P2A_5 2.2,5.52 ; CONNB1.P2A_5 3.64,5.52 ; 78.95,5.52 CONNB2.P1A_4 ; CONNB2.P1A_4 79.67,7.18 ; CONNB2.P1A_4 80.61,6.24 ; CONNB2.P1A_4 80.39,5.52 ; CONNB2.P1A_4 78.95,6.96 ; CONNB2.P1A_4 80.39,6.96 ; CONNB2.P1A_4 78.73,6.24 ; CONNB2.P1A_4 79.67,5.3 ; CONNB1.P2A_3 8.86,6.24 ; CONNB1.P2A_3 7.2,6.96 ; CONNB1.P2A_3 8.64,6.96 ; CONNB1.P2A_3 7.92,5.3 ; CONNB1.P2A_3 7.2,5.52 ; CONNB1.P2A_3 6.98,6.24 ; CONNB1.P2A_3 8.64,5.52 ; CONNB1.P2A_3 7.92,7.18 ; 86.23,6.24 CONNB2.P1A_1 ; CONNB2.P1A_1 87.17,7.18 ; CONNB2.P1A_1 87.89,6.96 ; CONNB2.P1A_1 86.45,5.52 ; CONNB2.P1A_1 87.89,5.52 ; CONNB2.P1A_1 87.17,5.3 ; CONNB2.P1A_1 86.45,6.96 ; CONNB2.P1A_1 88.11,6.24 ; 24.2,6.96 CONNB1.P1A_1 ; CONNB1.P1A_1 25.86,6.24 ; CONNB1.P1A_1 25.64,5.52 ; CONNB1.P1A_1 25.64,6.96 ; CONNB1.P1A_1 24.92,7.18 ; CONNB1.P1A_1 24.92,5.3 ; CONNB1.P1A_1 23.98,6.24 ; CONNB1.P1A_1 24.2,5.52 ; 81.46,6.96 CONNB2.P1A_3 ; CONNB2.P1A_3 81.46,5.52 ; CONNB2.P1A_3 82.17,5.3 ; CONNB2.P1A_3 81.23,6.24 ; CONNB2.P1A_3 83.11,6.24 ; CONNB2.P1A_3 82.17,7.18 ; CONNB2.P1A_3 82.89,6.96 ; CONNB2.P1A_3 82.89,5.52 ; CONNB1.P2A_4 6.14,6.96 ; CONNB1.P2A_4 5.42,5.3 ; CONNB1.P2A_4 4.7,6.96 ; CONNB1.P2A_4 5.42,7.18 ; CONNB1.P2A_4 4.7,5.52 ; CONNB1.P2A_4 6.36,6.24 ; CONNB1.P2A_4 6.14,5.52 ; CONNB1.P2A_4 4.48,6.24 ; CONNB2.P2A_5 65.17,7.18 ; CONNB2.P2A_5 64.45,6.96 ; CONNB2.P2A_5 65.89,5.52 ; CONNB2.P2A_5 64.45,5.52 ; CONNB2.P2A_5 65.89,6.96 ; CONNB2.P2A_5 66.11,6.24 ; CONNB2.P2A_5 64.23,6.24 ; CONNB2.P2A_5 65.17,5.3 ; 84.67,5.3 CONNB2.P1A_2 ; CONNB2.P1A_2 84.67,7.18 ; CONNB2.P1A_2 85.39,6.96 ; CONNB2.P1A_2 85.39,5.52 ; CONNB2.P1A_2 83.95,6.96 ; CONNB2.P1A_2 85.61,6.24 ; CONNB2.P1A_2 83.95,5.52 ; CONNB2.P1A_2 83.73,6.24 ; 70.17,5.3 CONNB2.P2A_3 ; CONNB2.P2A_3 70.89,6.96 ; CONNB2.P2A_3 70.89,5.52 ; CONNB2.P2A_3 69.23,6.24 ; CONNB2.P2A_3 69.45,5.52 ; CONNB2.P2A_3 71.11,6.24 ; CONNB2.P2A_3 69.45,6.96 ; CONNB2.P2A_3 70.17,7.18 ; CONNB1.P1A_5 15.64,6.96 ; CONNB1.P1A_5 13.98,6.24 ; CONNB1.P1A_5 15.64,5.52 ; CONNB1.P1A_5 14.2,6.96 ; CONNB1.P1A_5 14.2,5.52 ; CONNB1.P1A_5 14.92,5.3 ; CONNB1.P1A_5 15.86,6.24 ; CONNB1.P1A_5 14.92,7.18 ; 22.42,5.3 CONNB1.P1A_2 ; CONNB1.P1A_2 23.14,5.52 ; CONNB1.P1A_2 21.7,5.52 ; CONNB1.P1A_2 22.42,7.18 ; CONNB1.P1A_2 23.14,6.96 ; CONNB1.P1A_2 21.7,6.96 ; CONNB1.P1A_2 21.48,6.24 ; CONNB1.P1A_2 23.36,6.24 ; 76.46,6.96 CONNB2.P1A_5 ; CONNB2.P1A_5 76.46,5.52 ; CONNB2.P1A_5 76.23,6.24 ; CONNB2.P1A_5 77.17,7.18 ; CONNB2.P1A_5 77.17,5.3 ; CONNB2.P1A_5 77.89,5.52 ; CONNB2.P1A_5 78.11,6.24 ; CONNB2.P1A_5 77.89,6.96 ; 19.92,5.3 CONNB1.P1A_3 ; CONNB1.P1A_3 20.86,6.24 ; CONNB1.P1A_3 20.64,5.52 ; CONNB1.P1A_3 18.98,6.24 ; CONNB1.P1A_3 20.64,6.96 ; CONNB1.P1A_3 19.2,5.52 ; CONNB1.P1A_3 19.92,7.18 ; CONNB1.P1A_3 19.2,6.96 ; CONNB1.P2A_1 13.64,5.52 ; CONNB1.P2A_1 13.86,6.24 ; CONNB1.P2A_1 12.2,6.96 ; CONNB1.P2A_1 11.98,6.24 ; CONNB1.P2A_1 13.64,6.96 ; CONNB1.P2A_1 12.92,5.3 ; CONNB1.P2A_1 12.2,5.52 ; CONNB1.P2A_1 12.92,7.18 ; 66.73,6.24 CONNB2.P2A_4 ; CONNB2.P2A_4 67.67,7.18 ; CONNB2.P2A_4 68.39,5.52 ; CONNB2.P2A_4 66.95,5.52 ; CONNB2.P2A_4 68.61,6.24 ; CONNB2.P2A_4 66.95,6.96 ; CONNB2.P2A_4 67.67,5.3 ; CONNB2.P2A_4 68.39,6.96 ; CONNB1.P2A_2 11.36,6.24 ; CONNB1.P2A_2 9.48,6.24 ; CONNB1.P2A_2 11.14,5.52 ; CONNB1.P2A_2 10.42,5.3 ; CONNB1.P2A_2 11.14,6.96 ; CONNB1.P2A_2 9.7,6.96 ; CONNB1.P2A_2 9.7,5.52 ; CONNB1.P2A_2 10.42,7.18
  G7 w0.762: CONN20.5 45.21,44.39 ; CONN20.5 42.88,45.38 ; CONN20.5 43.22,46.37 ; CONN20.5 43.22,44.39 ; CONN20.5 45.21,46.37 ; CONN20.5 44.21,44.05 ; CONN20.5 45.55,45.38 ; CONN20.5 44.21,46.71 ; CONN20.2 58.15,45.38 ; CONN20.2 56.81,44.05 ; CONN20.2 57.81,44.39 ; CONN20.2 55.82,46.37 ; CONN20.2 55.82,44.39 ; CONN20.2 55.48,45.38 ; CONN20.2 57.81,46.37 ; CONN20.2 56.81,46.71 ; CONN20.17 45.21,49.89 ; CONN20.17 42.88,50.88 ; CONN20.17 45.21,51.87 ; CONN20.17 44.21,49.55 ; CONN20.17 43.22,51.87 ; CONN20.17 45.55,50.88 ; CONN20.17 43.22,49.89 ; CONN20.17 44.21,52.21 ; CONN20.14 57.81,49.89 ; CONN20.14 55.82,51.87 ; CONN20.14 57.81,51.87 ; CONN20.14 56.81,52.21 ; CONN20.14 55.48,50.88 ; CONN20.14 58.15,50.88 ; CONN20.14 56.81,49.55 ; CONN20.14 55.82,49.89 ; 31.61,49.55 CONN20.20 ; CONN20.20 32.61,51.87 ; CONN20.20 30.28,50.88 ; CONN20.20 30.62,51.87 ; CONN20.20 30.62,49.89 ; CONN20.20 31.61,52.21 ; CONN20.20 32.61,49.89 ; CONN20.20 32.95,50.88 ; 17.68,45.38 CONN20.11 ; CONN20.11 18.02,44.39 ; CONN20.11 20.01,44.39 ; CONN20.11 20.35,45.38 ; CONN20.11 20.01,46.37 ; CONN20.11 18.02,46.37 ; CONN20.11 19.01,46.71 ; CONN20.11 19.01,44.05 ; CONN20.8 31.61,46.71 ; CONN20.8 32.61,46.37 ; CONN20.8 32.95,45.38 ; CONN20.8 30.28,45.38 ; CONN20.8 30.62,44.39 ; CONN20.8 30.62,46.37 ; CONN20.8 31.61,44.05 ; CONN20.8 32.61,44.39 ; 13.48,50.88 CONN20.24 ; CONN20.24 15.81,51.87 ; CONN20.24 14.81,52.21 ; CONN20.24 13.82,49.89 ; CONN20.24 16.15,50.88 ; CONN20.24 13.82,51.87 ; CONN20.24 15.81,49.89 ; CONN20.24 14.81,49.55 ; 13.48,45.38 CONN20.12 ; CONN20.12 14.81,46.71 ; CONN20.12 15.81,46.37 ; CONN20.12 14.81,44.05 ; CONN20.12 15.81,44.39 ; CONN20.12 13.82,46.37 ; CONN20.12 13.82,44.39 ; CONN20.12 16.15,45.38 ; CONN20.23 19.01,52.21 ; CONN20.23 19.01,49.55 ; CONN20.23 18.02,49.89 ; CONN20.23 20.35,50.88 ; CONN20.23 20.01,51.87 ; CONN20.23 20.01,49.89 ; CONN20.23 17.68,50.88 ; CONN20.23 18.02,51.87
  BOTTOM w0.127: v2(54.19,30.4) 54,30.58 v1(54,31.37) ; v2(57.06,32.71) 56.36,33.4 v1(56.36,33.63)
  BOTTOM w0.381: Q4.A v2(45.55,17.74) ; v2(96.75,39.81) 97.02,39.54 RB5.1 ; R41.2 33.89,12.64 v2(33.79,12.54) ; C128.2 v2(57.03,27.73) ; C17.2 v2(36.41,39.03) ; v2(20.25,18.89) 20.49,18.66 C62.2 ; CB5.2 83.91,27.42 v2(84.41,27.93) ; R12.1 71.82,38.07 v2(72.4,37.48) ; v2(27.8,38.4) 27.26,38.93 C110.1 ; C37.1 38.62,24.68 38.35,24.95 v2(38.35,24.96) ; C46.2 65.29,16.22 ; R52.1 48.09,13.71 v2(48.37,13.99) ; v2(97.74,16.61) 97.27,16.14 RB17.1 ; v2(15.68,19.78) 15.63,19.83 RB21.2 ; v2(35.97,14.88) 35.97,14.97 35.27,14.97 35.13,15.11 R44.2 ; 40.55,38.93 40.6,38.98 C59.2 ; R78.2 36.71,30.62 v2(37.17,30.17) ; C31.2 v2(56.75,24.99) ; C120.2 C121.1 42.68,39.13 v2(43.98,37.84) ; v2(35.44,38.98) 35.37,39.06 C117.2 C116.1 ; v2(88.28,15.72) 88.24,15.72 88.21,15.75 88.21,16.29 Q6.A 89.01,16.27 89.01,15.64 89.29,15.36 R24.1 ; v2(20.56,21.61) 20.99,21.18 C58.1 ; C80.2 v2(25.16,23.67) ; C129.1 v2(55.51,23) ; C136.1 v2(69.46,24.09) ; C106.1 24.5,40.48 v2(25.26,41.24) ; C118.1 v2(55.97,38.6) ; Q7.A v2(32.69,17.98) ; v2(22.18,29.48) 22.39,29.28 C101.2 C99.2 ; C132.2 38.62,33.17 v2(39.2,32.58) 38.85,32.22 C133.1 ; v2(41.04,14.5) 41.04,14.51 41.54,15 R27.1 ; R18.1 v2(97.47,44.37) ; R42.1 v2(107.48,36.24) ; R38.1 v2(96.73,41.6) ; R54.2 30.36,15.48 v2(30.36,17.02) ; C35.2 v2(40.07,28.59) ; C127.2 C115.2 44.95,37.31 v2(44.74,37.1) ; C122.1 v2(55.94,39.64) ; C22.2 90.94,39.57 v2(90.92,39.59) ; C103.2 19.19,32.3 v2(19.59,32.71) ; C79.2 v2(26.63,23.59) ; Q3.A v2(41.41,17.94) ; QB2.A 84.43,15.18 RB14.2 85.05,15.03 v2(85.86,15.84) ; CB6.2 v2(85.91,27.83) ; R83.2 v2(72.68,28.54) ; C137.2 v2(39.38,27.27) ; CB9.1 13.45,27.81 v2(13.12,28.14) ; C51.2 v2(39.23,25.72) ; v2(19.31,18.97) 19.57,19.22 CB54.1 ; C105.2 v2(17.54,38.55) ; C96.2 v2(28.66,37.2) ; Q8.A v2(37.09,18.02) ; CB7.2 v2(89.19,26.87) ; C25.2 v2(56.75,26.46) ; C135.2 v2(71.34,23.74) ; R33.1 v2(44.71,13.48) ; R30.1 v2(107.54,43.43) ; R48.1 v2(107.57,40.35) ; R20.1 v2(107.49,38.3)
  vias: v1(10.29,33.43) v1(10.41,35.51) v1(22.66,34.07) v1(22.81,35.97) v1(37.78,26) v1(38.06,28.14) v1(38.4,36.35) v1(42.45,35.78) v1(55.51,27.6) v1(55.56,24.99) v1(63.96,16.59) v1(77.52,42.88) v1(77.88,36.7) v2(1.33,53.28) v2(1.33,45.66) v2(1.33,43.12) v2(1.33,40.58) v2(1.33,38.04) v2(1.33,35.5) v2(1.33,32.96) v2(1.33,30.42) v2(1.33,27.88) v2(1.33,25.34) v2(1.33,22.8) v2(1.33,20.26) v2(1.33,12.64) v2(1.33,7.56) v2(1.33,5.02) v2(1.33,2.48) v2(2.19,1.44) v2(4.07,53.69) v2(4.73,1.44) v2(6.61,53.69) v2(7.27,1.44) v2(9.15,53.69) v2(9.81,1.44) v2(11.69,53.69) v2(11.92,14.09) v2(12.05,17.02) v2(12.35,1.44) v2(13.02,17.02) v2(12.96,14.09) v2(13.83,14.09) v2(13.96,17.04) v2(14.23,53.69) v2(14.89,1.44) v2(16.77,53.69) v2(17.43,1.44) v2(19.31,53.69) v2(19.97,1.44) v2(21.85,53.69) v2(22.51,1.44) v2(24.39,53.69) v2(25.05,1.44) v2(26.93,53.69) v2(27.11,15.51) v2(27.11,14.32) v2(27.59,1.44) v2(28.1,17.02) v2(28.13,14.24) v2(29.32,17.02) v2(29.47,53.69) v2(30.13,1.44) v2(32.01,53.69) v2(32.67,1.44) v2(34.55,53.69) v2(35.21,1.44) v2(37.09,53.69) v2(37.75,1.44) v2(39.63,53.69) v2(40.29,1.44) v2(42.17,53.69) v2(42.83,1.44) v2(44.71,53.69) v2(45.37,1.44) v2(47.25,53.69) v2(47.91,1.44) v2(49.79,53.69) v2(50.45,1.44) v2(52.33,53.69) v2(52.99,1.44) v2(54.87,53.69) v2(55.05,32.78) v2(55.18,32) v2(55.33,35.27) v2(55.53,1.44) v2(55.99,37.1) v2(56.09,31.97) v2(56.2,34.94) v2(56.91,37.58) v2(57.26,35.22) v2(57.41,53.69) v2(58.07,1.44) v2(59.95,53.69) v2(60.61,1.44) v2(62.49,53.69) v2(64.63,14.57) v2(64.81,39.62) v2(65.03,53.69) v2(65.01,17.21) v2(65.16,40.76) v2(65.82,14.62) v2(65.9,39.62) v2(66.15,17.26) v2(66.94,14.67) v2(67.02,40.84) v2(67.02,34.89) v2(67.09,17.26) v2(67.57,53.69) v2(67.93,39.62) v2(68.11,40.91) v2(68.44,34.99) v2(68.62,38.27) v2(69.15,37.25) v2(69.43,34.92) v2(70.6,32.91) v2(70.57,31.34) v2(72.65,53.69) v2(74.96,30.2) v2(75.19,53.69) v2(77.73,53.69) v2(80.27,53.69) v2(80.91,17.29) v2(81.06,14.72) v2(81.8,17.32) v2(81.8,14.75) v2(82.56,14.8) v2(82.81,53.69) v2(82.87,17.32) v2(83.47,1.44) v2(85.35,53.69) v2(86.01,1.44) v2(87.89,53.69) v2(88.55,1.44) v2(90.43,53.69) v2(91.09,1.44) v2(92.97,53.69) v2(93.63,1.44) v2(95.51,53.69) v2(96.17,1.44) v2(98.05,53.69) v2(98.71,1.44) v2(100.59,53.69) v2(101.25,1.44) v2(103.13,53.69) v2(103.79,1.44) v2(105.67,53.69) v2(106.33,1.44) v2(107.5,33.06) v2(107.5,30.52) v2(107.5,27.98) v2(107.5,25.44) v2(107.5,22.9) v2(107.5,20.36) v2(107.5,12.74) v2(107.5,10.2) v2(107.5,7.66) v2(107.5,5.12) v2(107.5,2.58) v2(107.58,53.41) v2(107.58,50.87) v2(107.58,48.33) v2(107.58,45.79) v3(12.65,35.62) v3(12.65,34.47) v3(13.79,35.62) v3(15.9,24.6) v3(15.9,23.71) v3(16.81,24.6) v3(16.81,23.71) v3(24.76,35.44) v3(24.76,34.3) v3(25.91,35.44) v3(77.96,41.15) v3(77.96,40.21) v3(77.96,39.27) v3(77.96,38.33) v3(78.88,41.15) v3(78.88,40.21) v3(78.88,39.27) v3(78.88,38.33) v3(84.29,34.16) v3(84.29,33.27) v3(85.2,34.16) v3(85.2,33.27)
